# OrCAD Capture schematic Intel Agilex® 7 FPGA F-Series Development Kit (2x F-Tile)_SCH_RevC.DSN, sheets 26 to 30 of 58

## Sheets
26 PG29 HPS DDR4 COMP3,4: size C
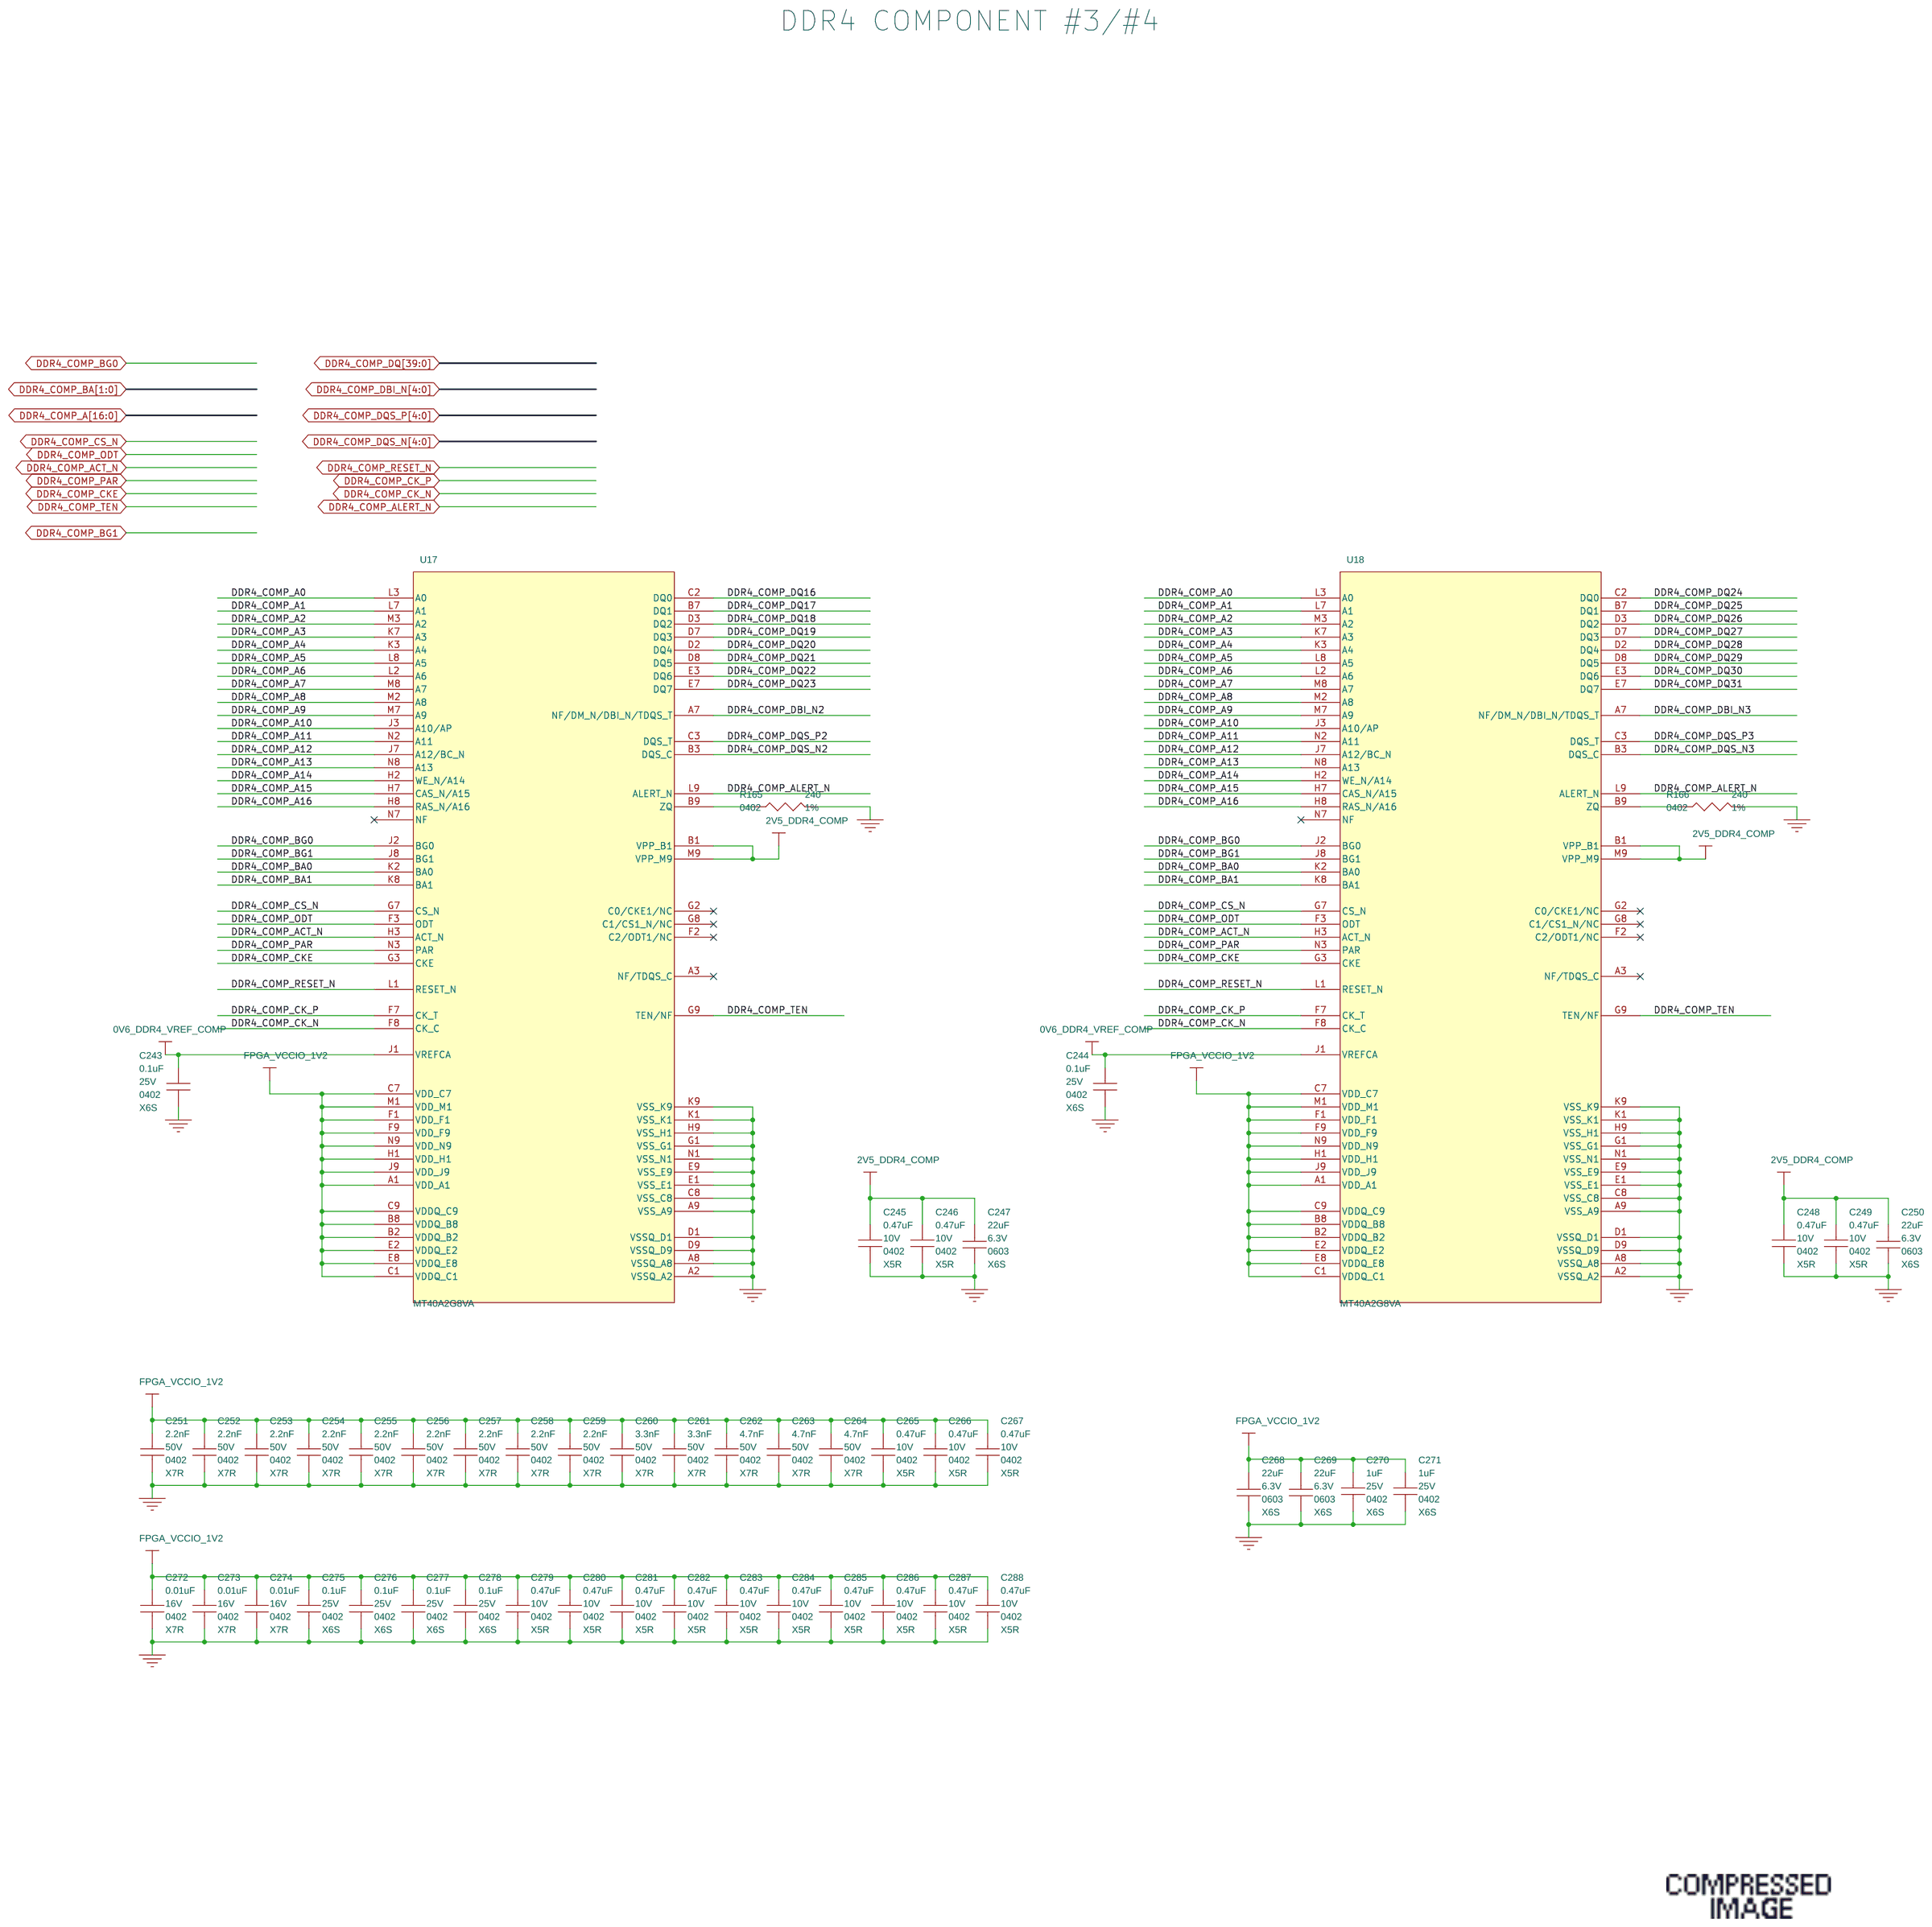
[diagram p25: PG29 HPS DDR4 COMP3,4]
27 PG30 HPSDDR4 COMP5, TERM: size C
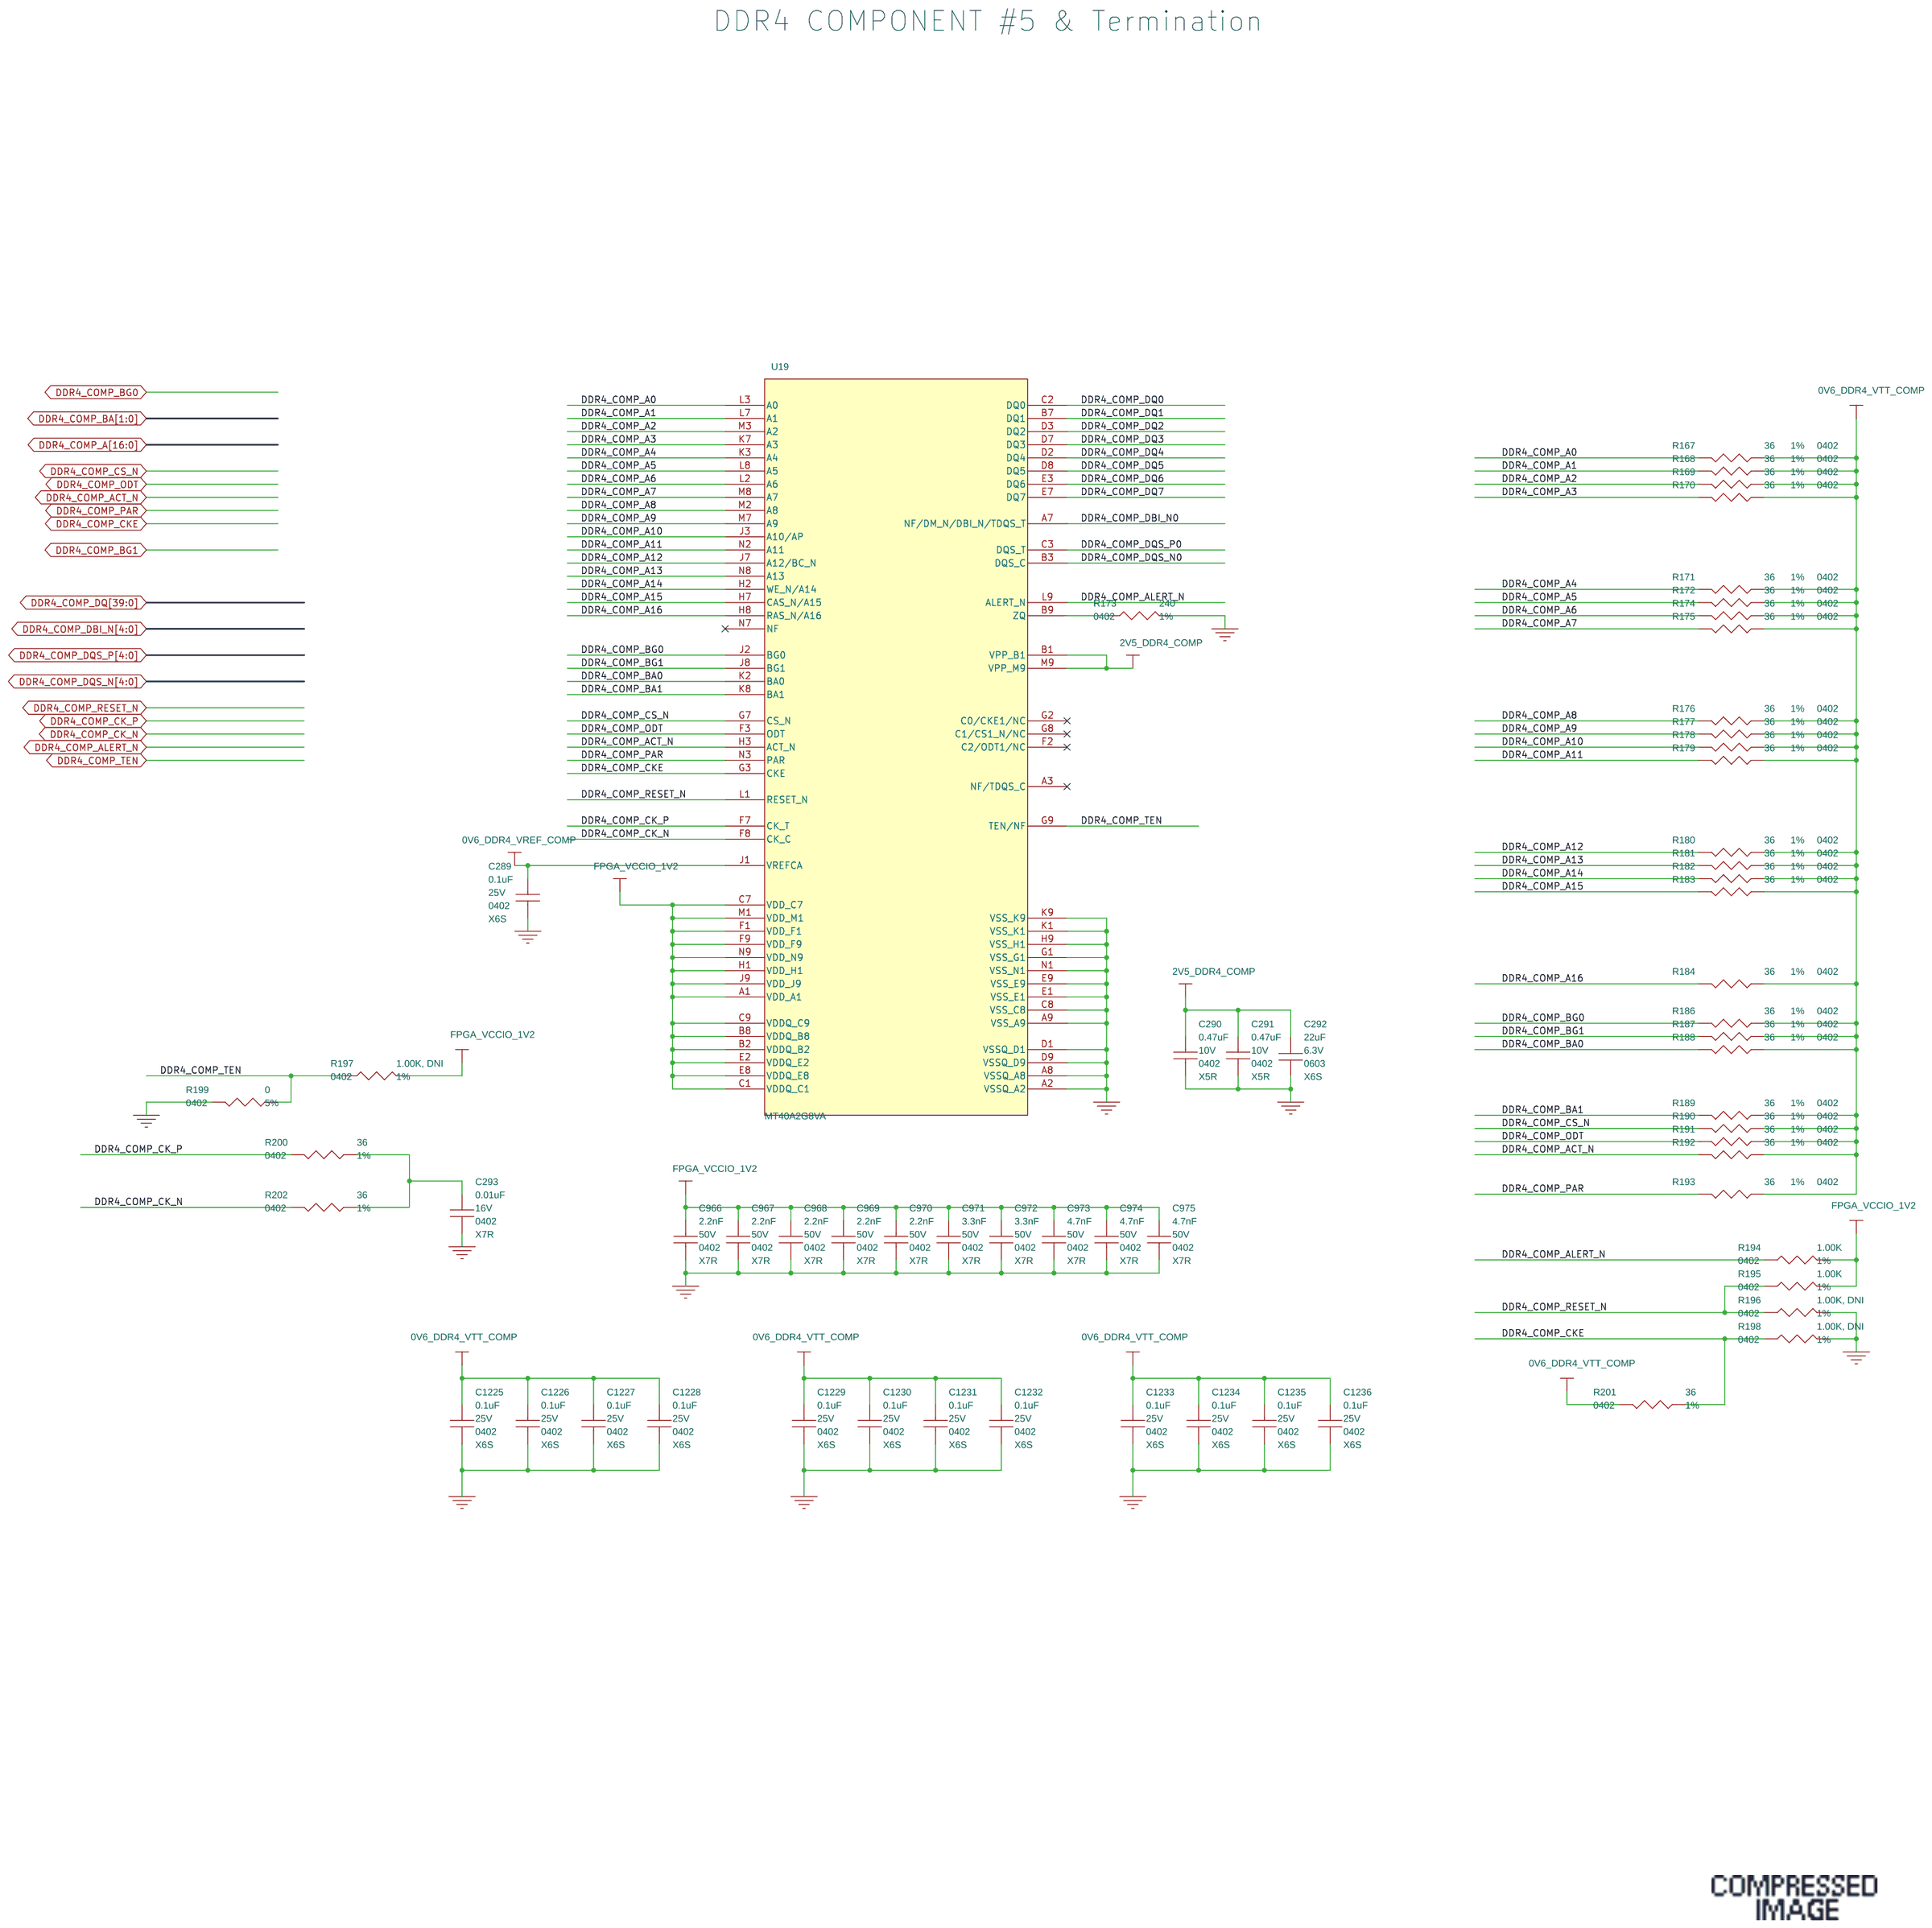
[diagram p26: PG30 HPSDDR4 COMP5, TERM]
28 PG31 HPS IO48 INTERFACE: size C
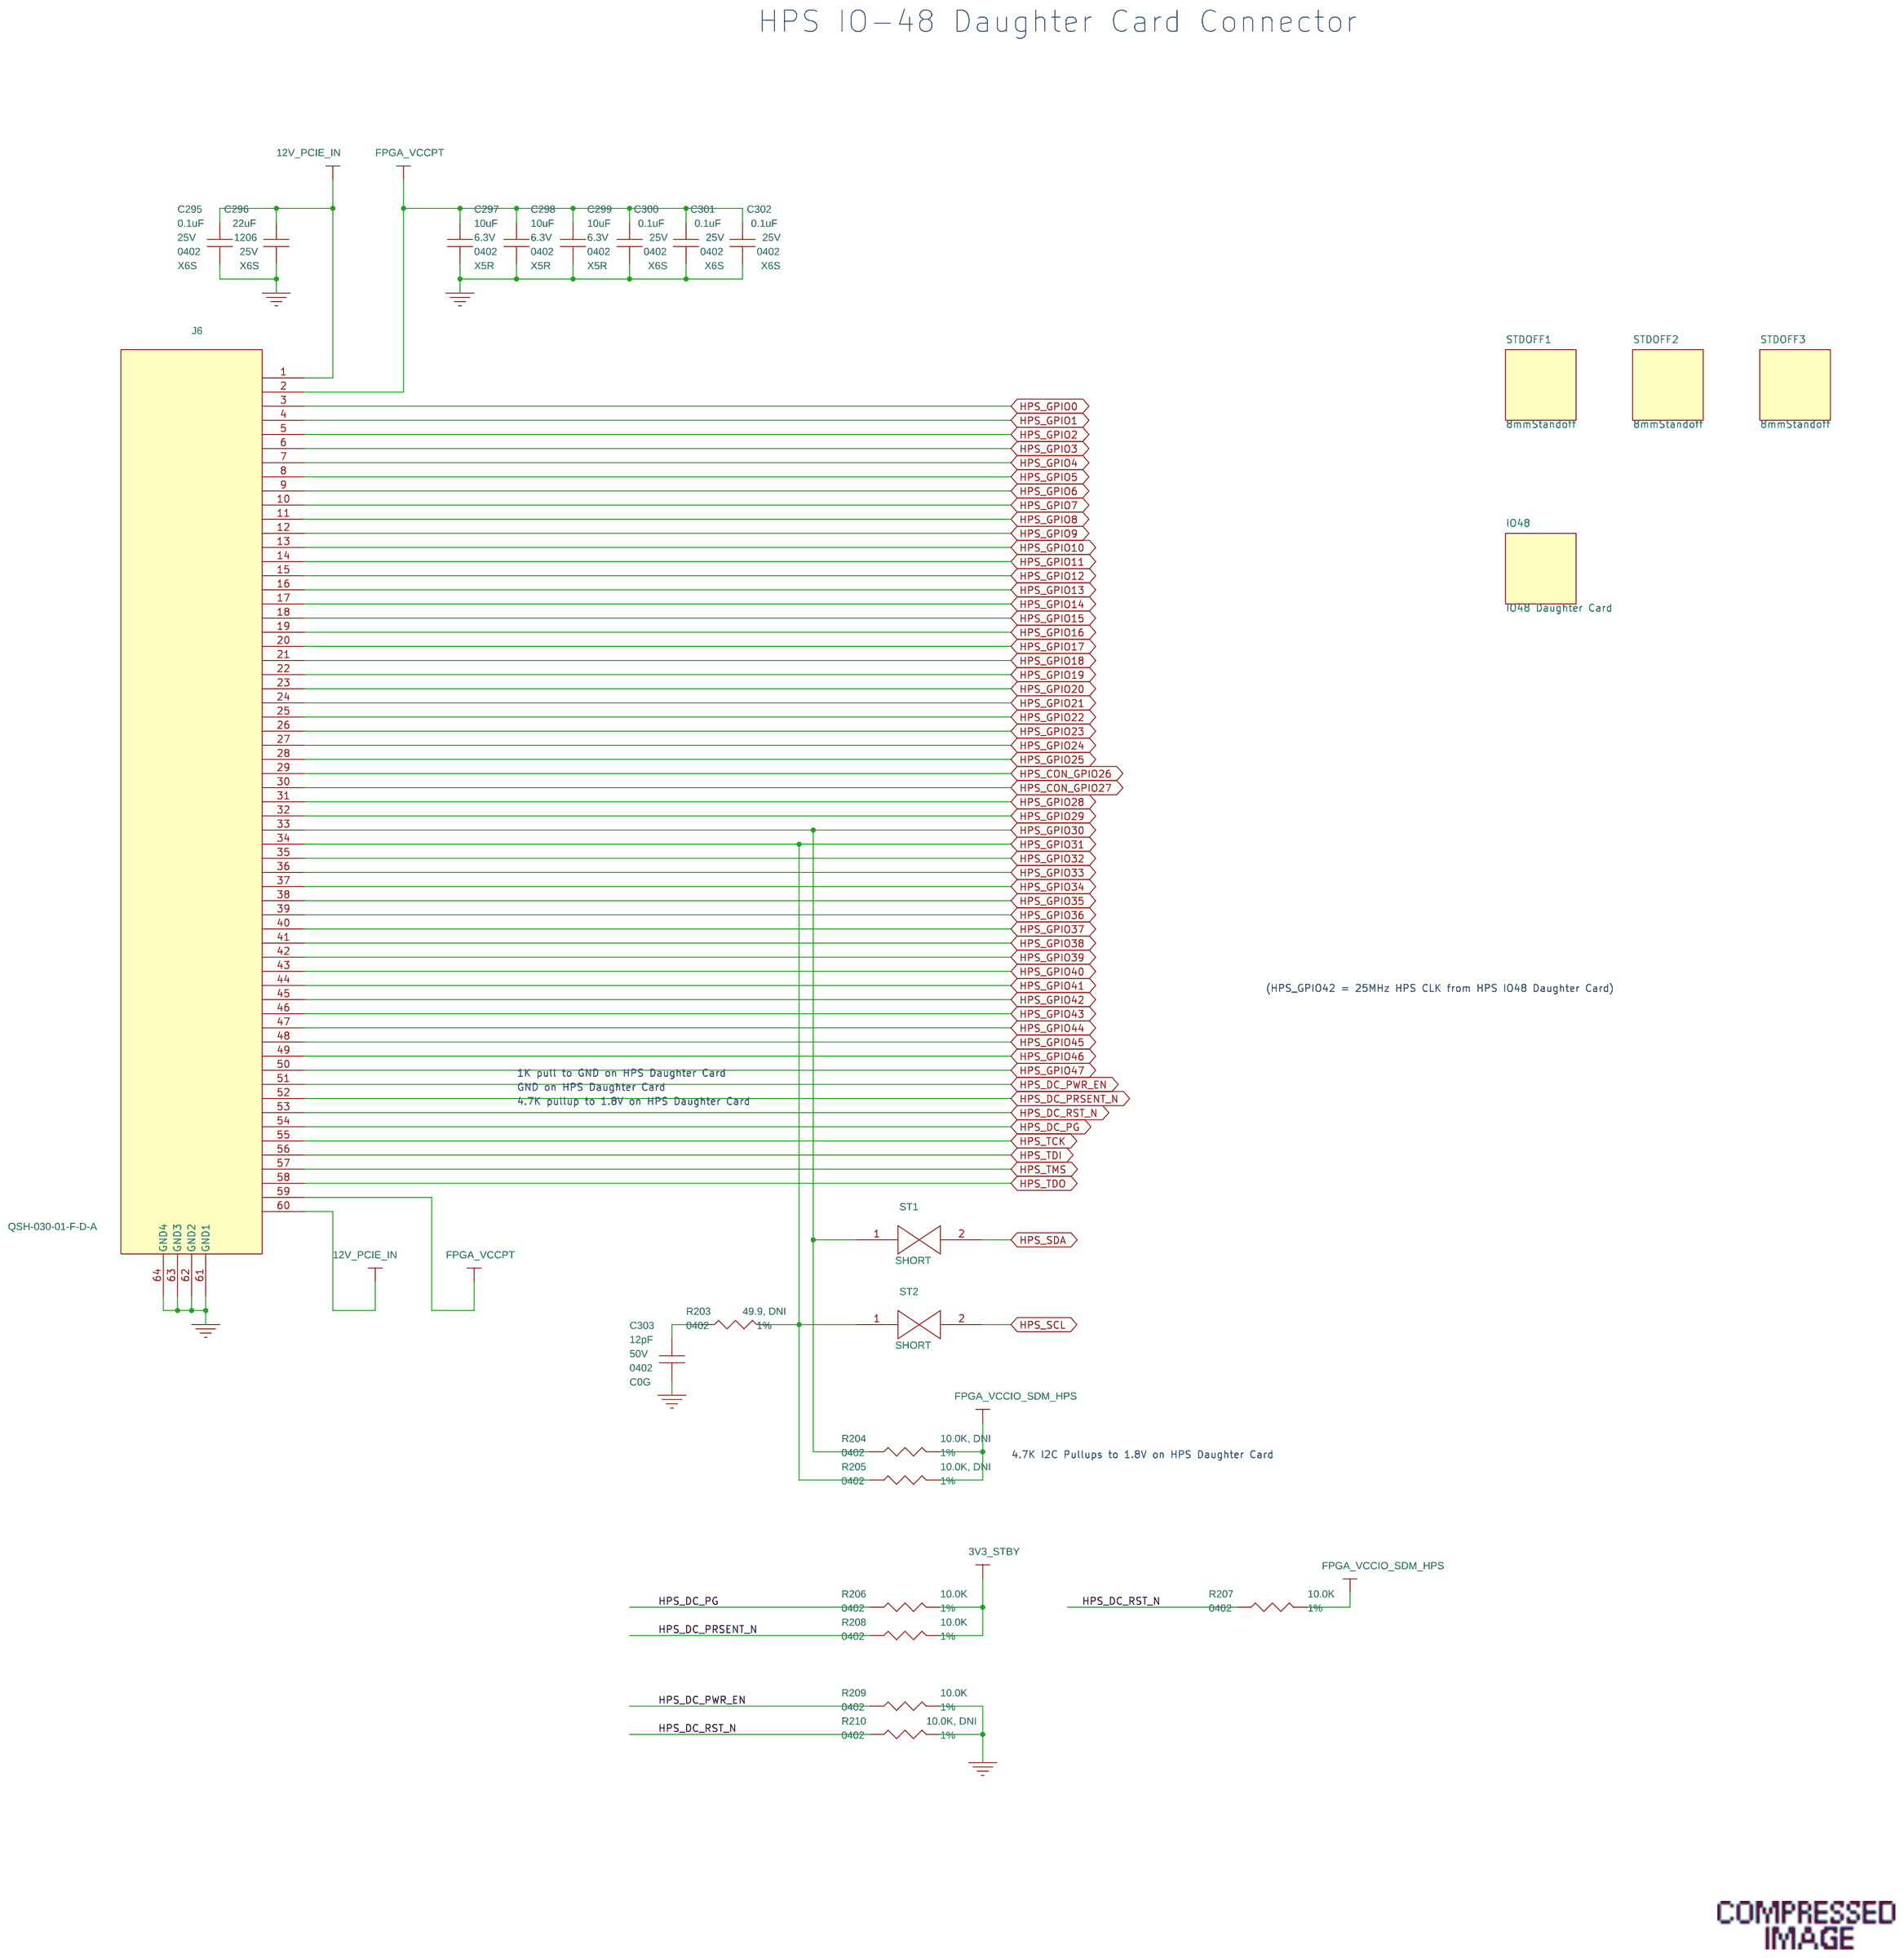
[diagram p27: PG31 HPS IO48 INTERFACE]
29 PG32 QSFPDD-56: size C
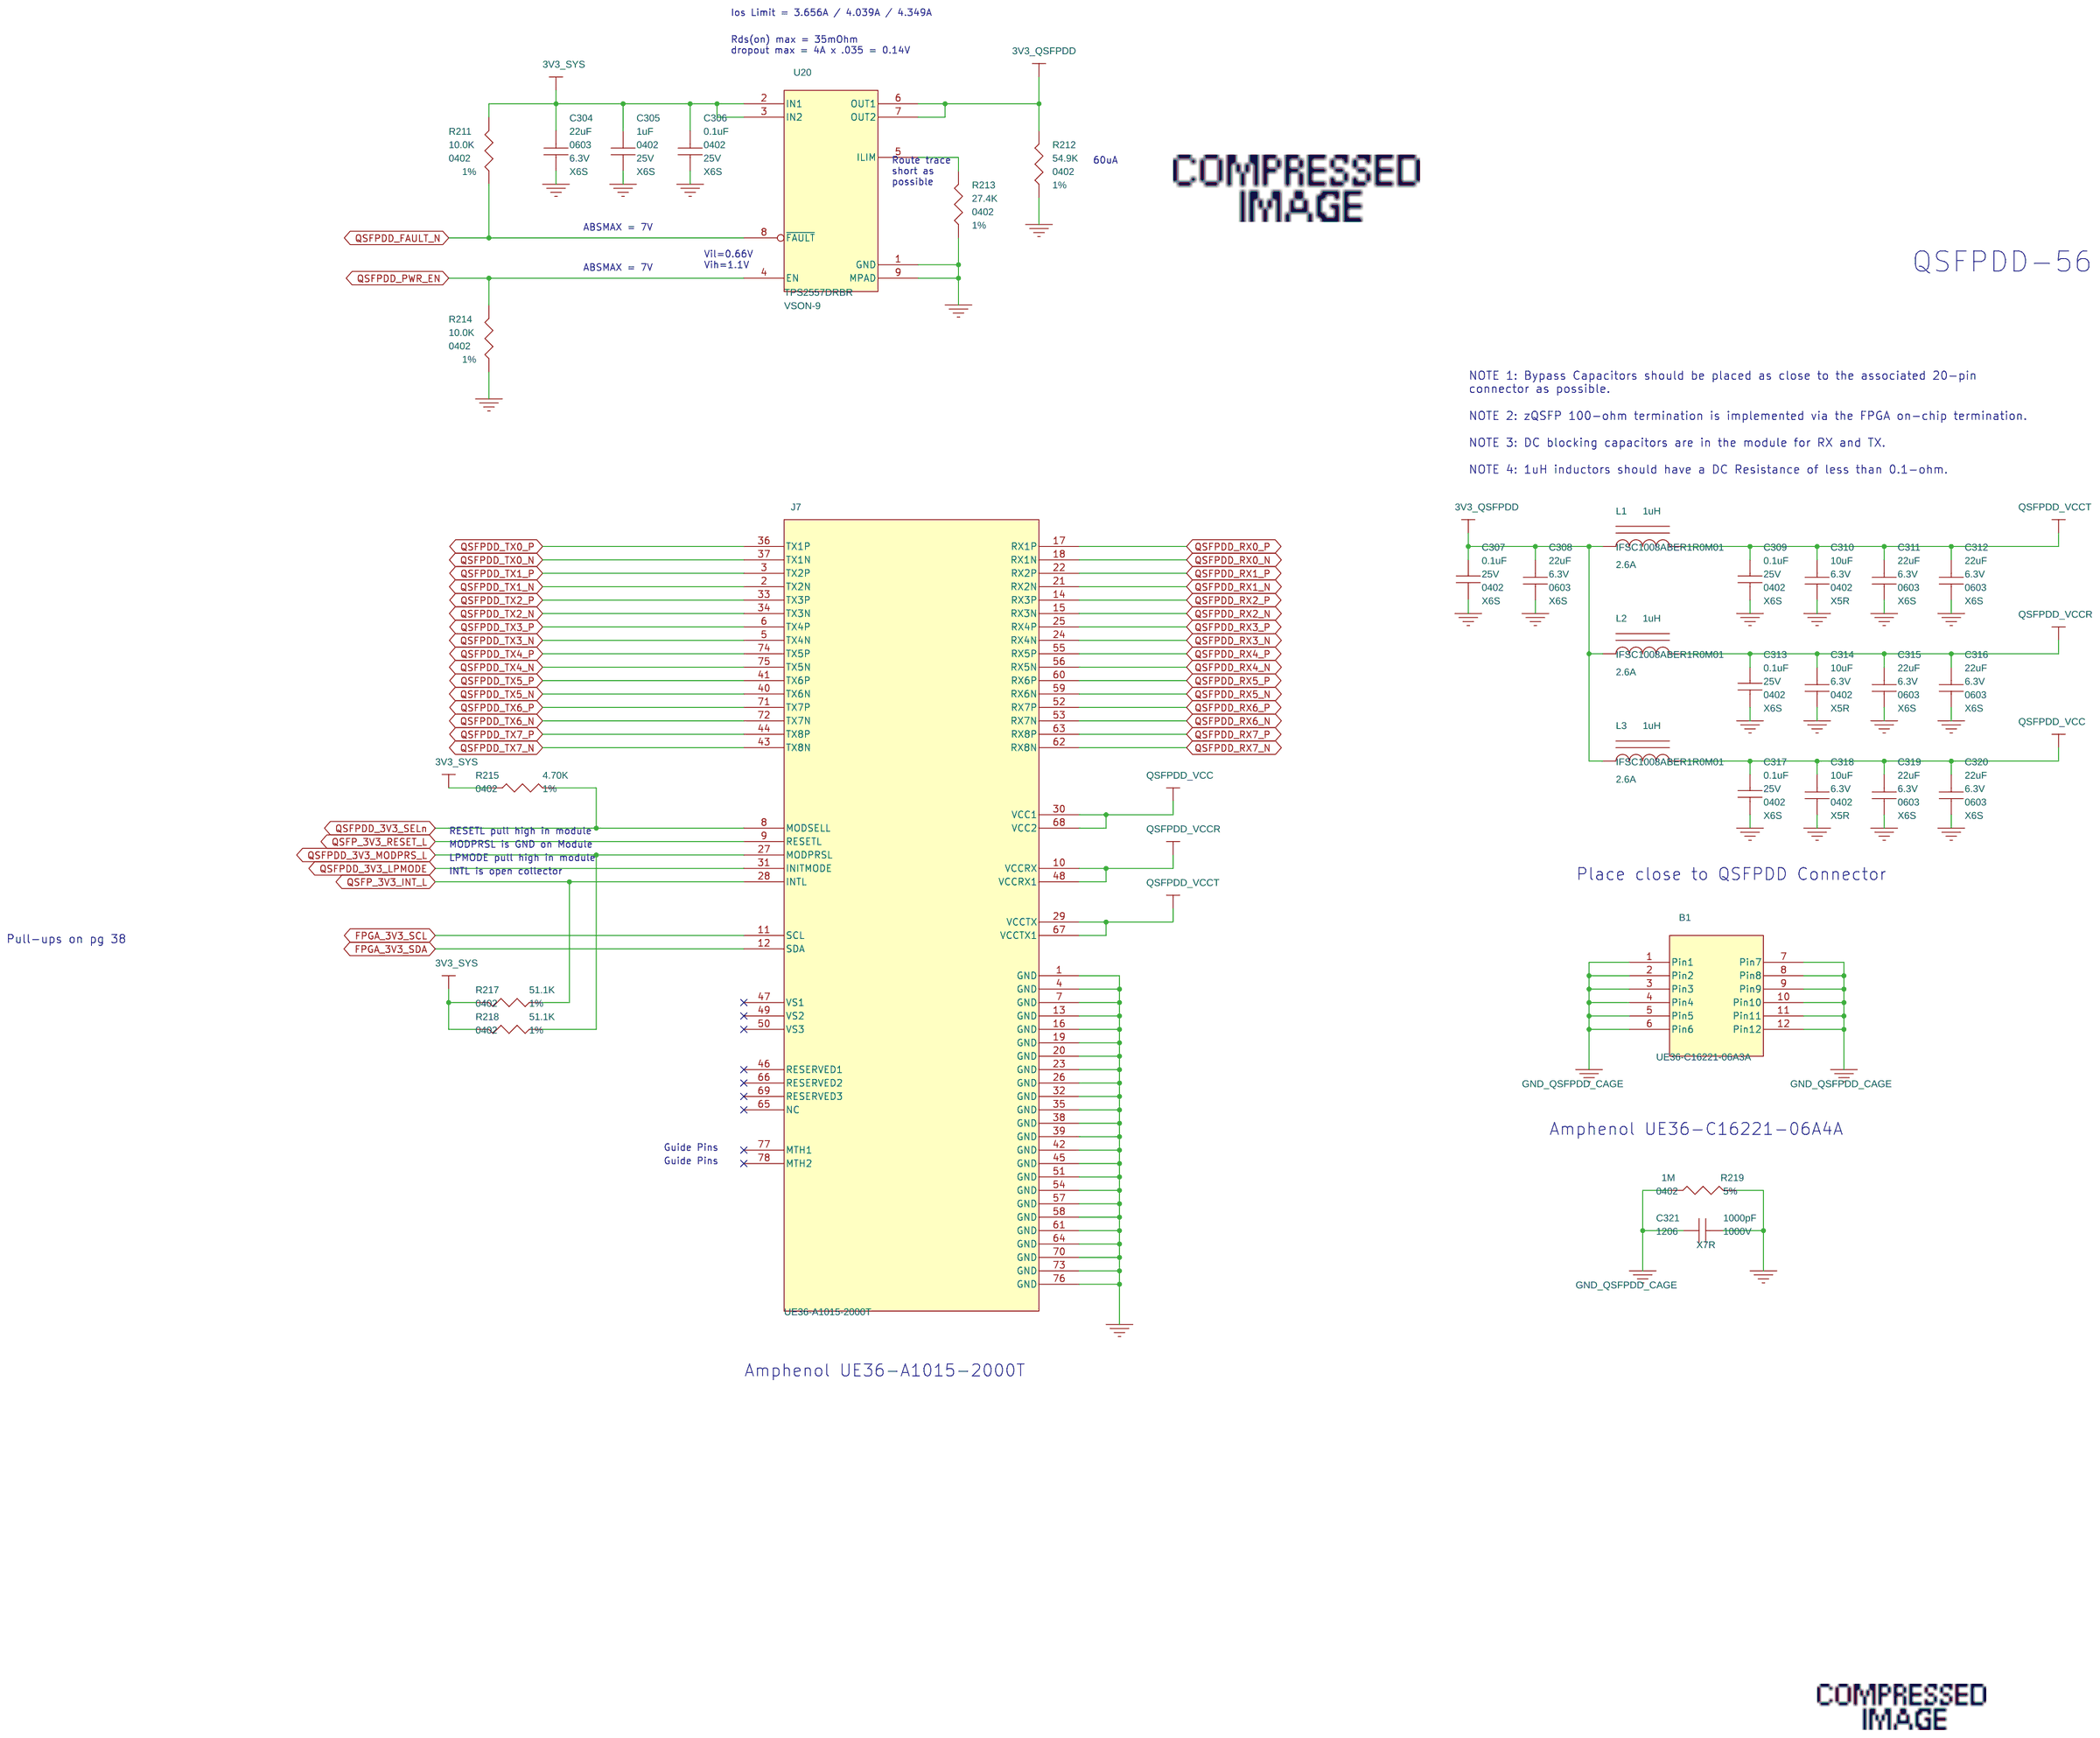
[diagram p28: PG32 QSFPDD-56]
30 PG33 QSFP-56: size C
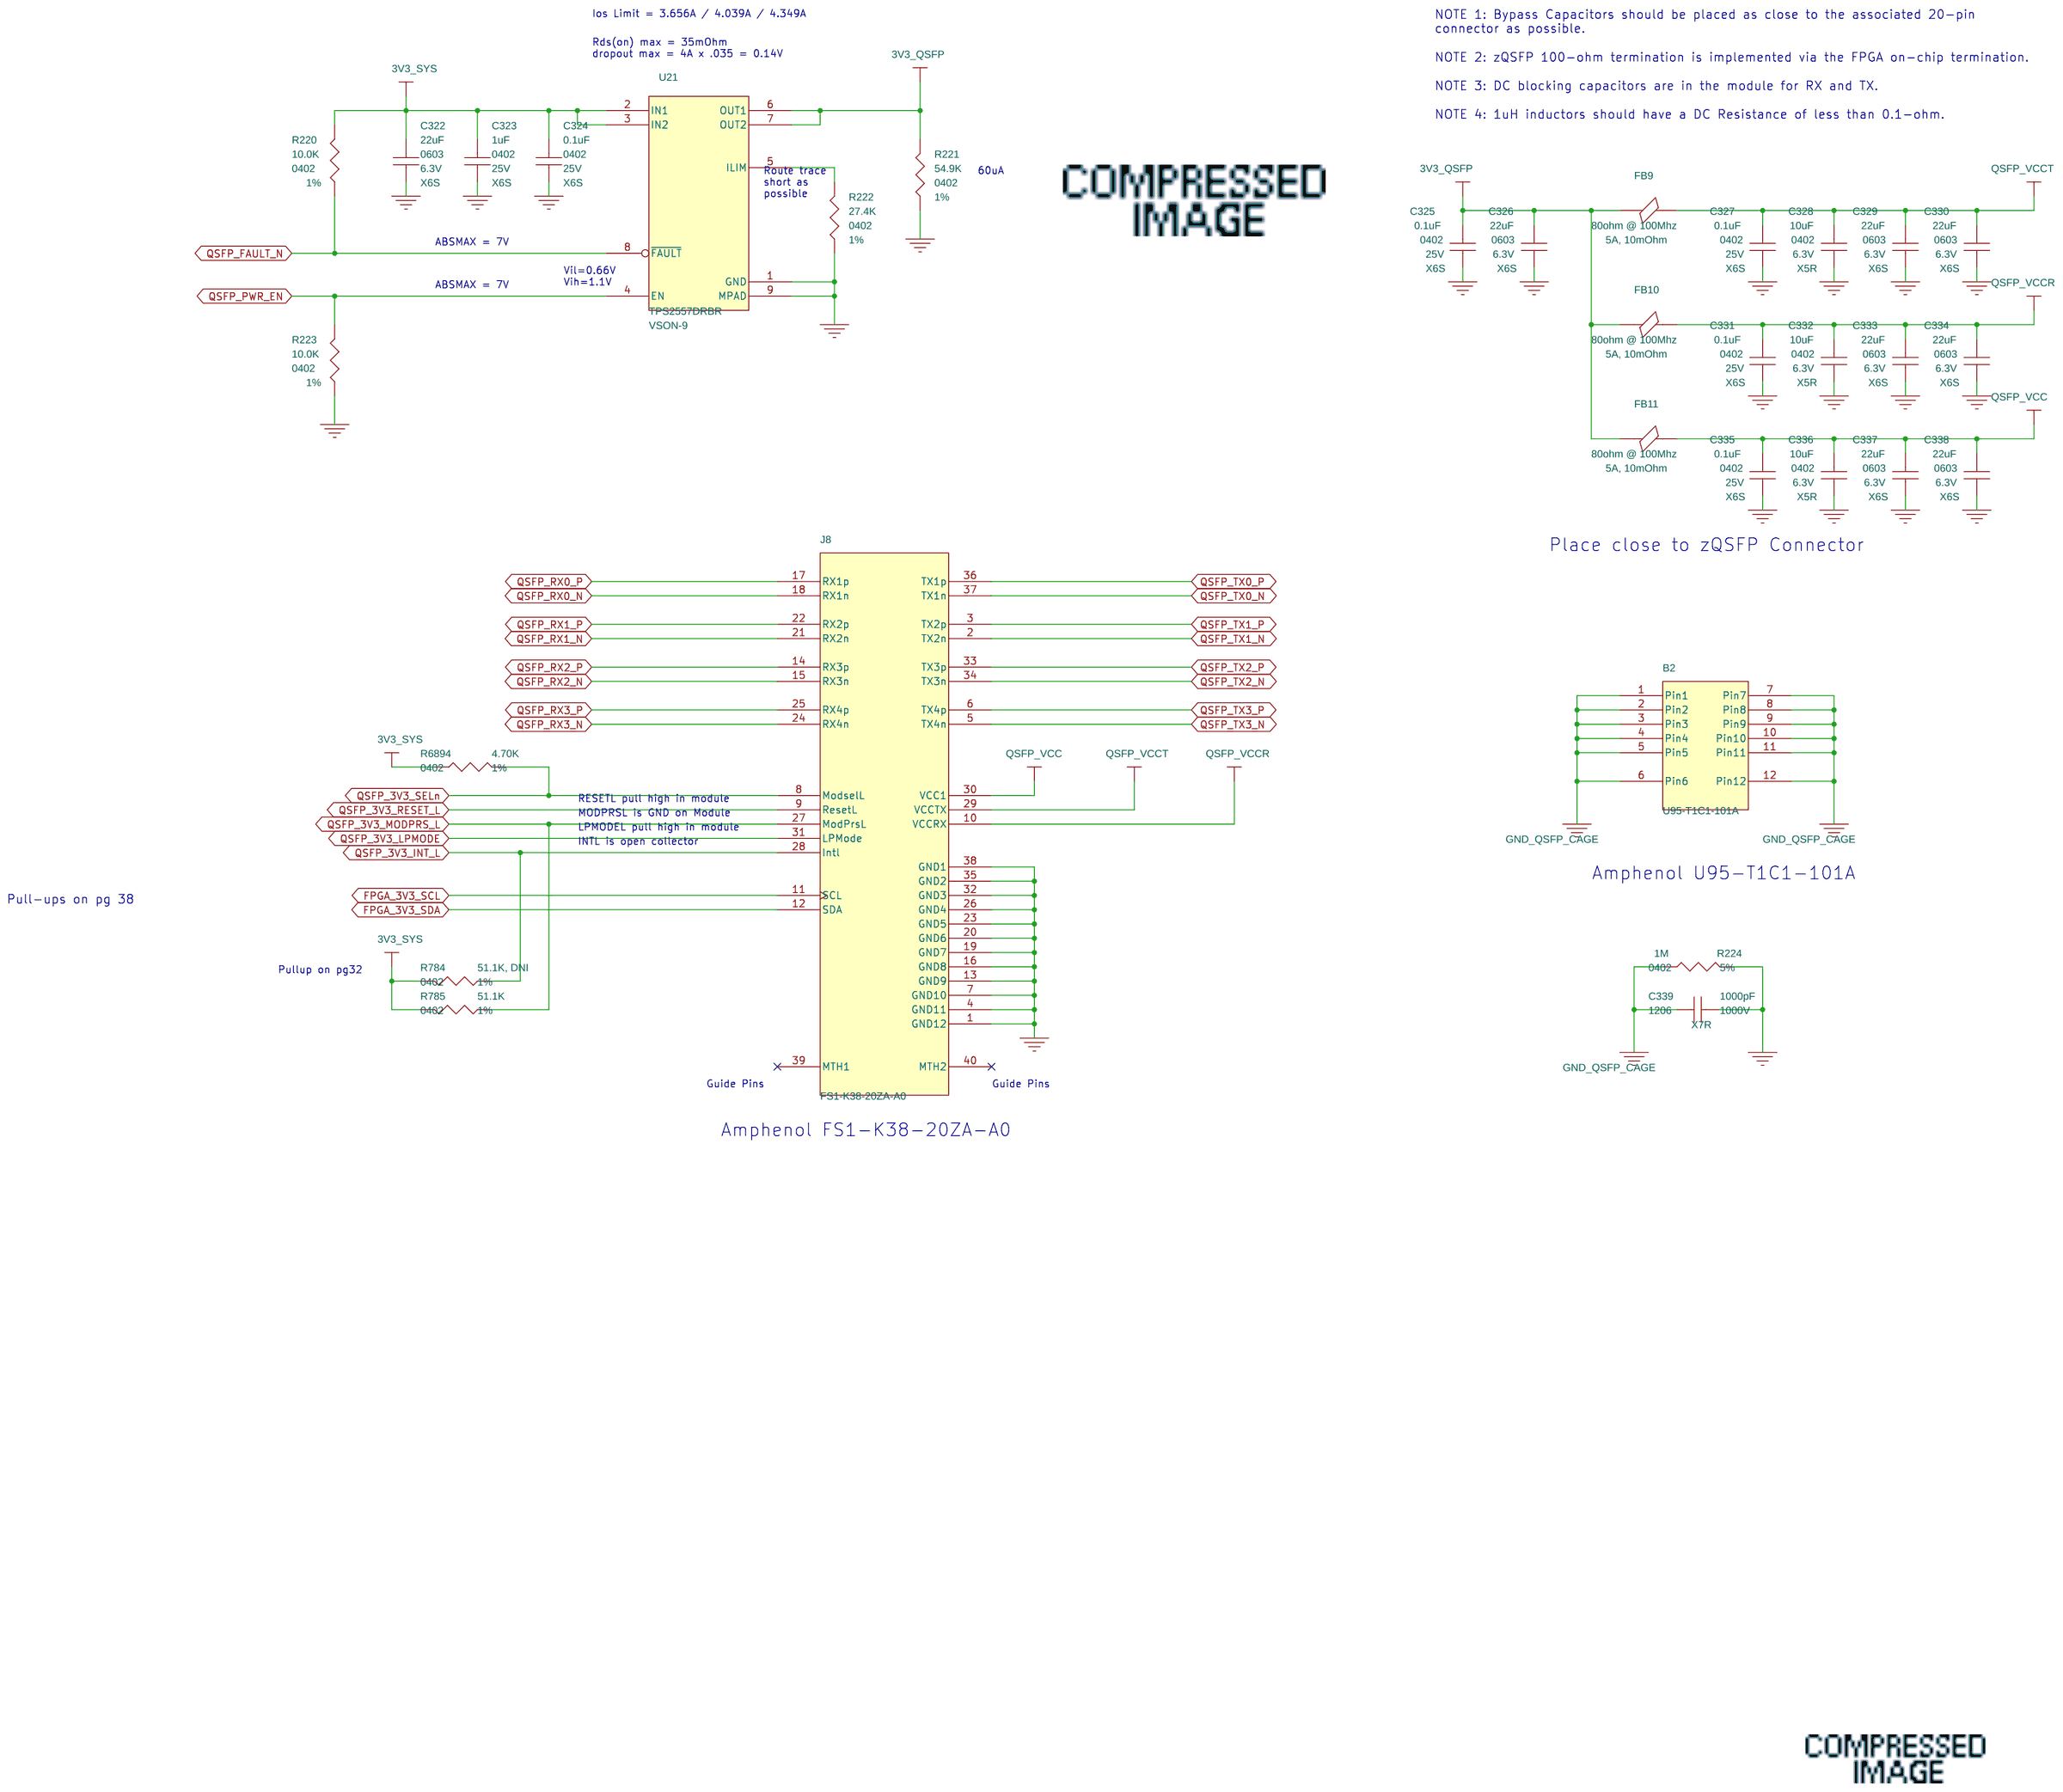
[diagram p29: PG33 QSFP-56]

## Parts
sheet PG29 HPS DDR4 COMP3,4
C243  0.1uF  [0402]
C244  0.1uF  [0402]
C245  0.47uF  [0402]
C246  0.47uF  [0402]
C247  22uF  [0603]
C248  0.47uF  [0402]
C249  0.47uF  [0402]
C250  22uF  [0603]
C251  2.2nF  [0402]
C252  2.2nF  [0402]
C253  2.2nF  [0402]
C254  2.2nF  [0402]
C255  2.2nF  [0402]
C256  2.2nF  [0402]
C257  2.2nF  [0402]
C258  2.2nF  [0402]
C259  2.2nF  [0402]
C260  3.3nF  [0402]
C261  3.3nF  [0402]
C262  4.7nF  [0402]
C263  4.7nF  [0402]
C264  4.7nF  [0402]
C265  0.47uF  [0402]
C266  0.47uF  [0402]
C267  0.47uF  [0402]
C268  22uF  [0603]
C269  22uF  [0603]
C270  1uF  [0402]
C271  1uF  [0402]
C272  0.01uF  [0402]
C273  0.01uF  [0402]
C274  0.01uF  [0402]
C275  0.1uF  [0402]
C276  0.1uF  [0402]
C277  0.1uF  [0402]
C278  0.1uF  [0402]
C279  0.47uF  [0402]
C280  0.47uF  [0402]
C281  0.47uF  [0402]
C282  0.47uF  [0402]
C283  0.47uF  [0402]
C284  0.47uF  [0402]
C285  0.47uF  [0402]
C286  0.47uF  [0402]
C287  0.47uF  [0402]
C288  0.47uF  [0402]
R165  240  [0402]
R166  240  [0402]
U17  MT40A2G8VA  [FBGA-78]
U18  MT40A2G8VA  [FBGA-78]
sheet PG30 HPSDDR4 COMP5, TERM
C289  0.1uF  [0402]
C290  0.47uF  [0402]
C291  0.47uF  [0402]
C292  22uF  [0603]
C293  0.01uF  [0402]
C966  2.2nF  [0402]
C967  2.2nF  [0402]
C968  2.2nF  [0402]
C969  2.2nF  [0402]
C970  2.2nF  [0402]
C971  3.3nF  [0402]
C972  3.3nF  [0402]
C973  4.7nF  [0402]
C974  4.7nF  [0402]
C975  4.7nF  [0402]
C1225  0.1uF  [0402]
C1226  0.1uF  [0402]
C1227  0.1uF  [0402]
C1228  0.1uF  [0402]
C1229  0.1uF  [0402]
C1230  0.1uF  [0402]
C1231  0.1uF  [0402]
C1232  0.1uF  [0402]
C1233  0.1uF  [0402]
C1234  0.1uF  [0402]
C1235  0.1uF  [0402]
C1236  0.1uF  [0402]
R167  36  [0402]
R168  36  [0402]
R169  36  [0402]
R170  36  [0402]
R171  36  [0402]
R172  36  [0402]
R173  240  [0402]
R174  36  [0402]
R175  36  [0402]
R176  36  [0402]
R177  36  [0402]
R178  36  [0402]
R179  36  [0402]
R180  36  [0402]
R181  36  [0402]
R182  36  [0402]
R183  36  [0402]
R184  36  [0402]
R186  36  [0402]
R187  36  [0402]
R188  36  [0402]
R189  36  [0402]
R190  36  [0402]
R191  36  [0402]
R192  36  [0402]
R193  36  [0402]
R194  1.00K  [0402]
R195  1.00K  [0402]
R196  1.00K, DNI  [0402]
R197  1.00K, DNI  [0402]
R198  1.00K, DNI  [0402]
R199  0  [0402]
R200  36  [0402]
R201  36  [0402]
R202  36  [0402]
U19  MT40A2G8VA  [FBGA-78]
sheet PG31 HPS IO48 INTERFACE
C295  0.1uF  [0402]
C296  22uF  [1206]
C297  10uF  [0402]
C298  10uF  [0402]
C299  10uF  [0402]
C300  0.1uF  [0402]
C301  0.1uF  [0402]
C302  0.1uF  [0402]
C303  12pF  [0402]
IO48  IO48 Daughter Card
J6  QSH-030-01-F-D-A  [QSH-030-01-C-D-A]
R203  49.9, DNI  [0402]
R204  10.0K, DNI  [0402]
R205  10.0K, DNI  [0402]
R206  10.0K  [0402]
R207  10.0K  [0402]
R208  10.0K  [0402]
R209  10.0K  [0402]
R210  10.0K, DNI  [0402]
ST1  SHORT  [SHORT]
ST2  SHORT  [SHORT]
STDOFF1  8mmStandoff
STDOFF2  8mmStandoff
STDOFF3  8mmStandoff
sheet PG32 QSFPDD-56
B1  UE36-C16221-06A3A  [QSFPDD_Cage_UE36-C16221-06A3A]
C304  22uF  [0603]
C305  1uF  [0402]
C306  0.1uF  [0402]
C307  0.1uF  [0402]
C308  22uF  [0603]
C309  0.1uF  [0402]
C310  10uF  [0402]
C311  22uF  [0603]
C312  22uF  [0603]
C313  0.1uF  [0402]
C314  10uF  [0402]
C315  22uF  [0603]
C316  22uF  [0603]
C317  0.1uF  [0402]
C318  10uF  [0402]
C319  22uF  [0603]
C320  22uF  [0603]
C321  1000pF  [1206]
J7  UE36-A1015-2000T  [UE36-A1015-2000T]
L1  1uH  [IFSC1008ABER1R0M01]
L2  1uH  [IFSC1008ABER1R0M01]
L3  1uH  [IFSC1008ABER1R0M01]
R211  10.0K  [0402]
R212  54.9K  [0402]
R213  27.4K  [0402]
R214  10.0K  [0402]
R215  4.70K  [0402]
R217  51.1K  [0402]
R218  51.1K  [0402]
R219  1M  [0402]
U20  TPS2557DRBR  [VSON-9]
sheet PG33 QSFP-56
B2  U95-T1C1-101A  [zQSFP_Cage_U95-T1C1-101A]
C322  22uF  [0603]
C323  1uF  [0402]
C324  0.1uF  [0402]
C325  0.1uF  [0402]
C326  22uF  [0603]
C327  0.1uF  [0402]
C328  10uF  [0402]
C329  22uF  [0603]
C330  22uF  [0603]
C331  0.1uF  [0402]
C332  10uF  [0402]
C333  22uF  [0603]
C334  22uF  [0603]
C335  0.1uF  [0402]
C336  10uF  [0402]
C337  22uF  [0603]
C338  22uF  [0603]
C339  1000pF  [1206]
FB9  80ohm @ 100Mhz  [0805]
FB10  80ohm @ 100Mhz  [0805]
FB11  80ohm @ 100Mhz  [0805]
J8  FS1-K38-20ZA-A0  [FS1-K38-20ZA-A0]
R220  10.0K  [0402]
R221  54.9K  [0402]
R222  27.4K  [0402]
R223  10.0K  [0402]
R224  1M  [0402]
R784  51.1K, DNI  [0402]
R785  51.1K  [0402]
R6894  4.70K  [0402]
U21  TPS2557DRBR  [VSON-9]

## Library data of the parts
C243 C244 C275-C278 C289 C295 C300-C302 C306 C307 C309 C313 C317 C324 C325 C327 C331 C335 = CAP: CAP CER 0.1UF 25V X6S 0402; Dielectric: X6S; IPN: K19434-001; Item Num: K19434-001; LIFECYCLE_PHASE: Active; Lead Free Status: Lead Free; MFR_LIFECYCLE: Active; Manufacturer: Murata; Manufacturer Part Num: GRM155C81E104KA12D; Num Pins: 2; PART_SUBCLASS: CAPACITORS; Part Class: CAPACITORS; RATED_VOLTAGE: 25V; RoHS Compliant: RoHS Compliant; Temperature Coefficient: X6S; Tolerance: 10%
C245 C246 C248 C249 C265-C267 C279-C288 C290 C291 = CAP: CAP - CER, .47UF, 10V, X5R, 0402; AGILE_LINK: http://sj-agile9app/Agile/PLMServlet?action=OpenEmailObject&classid=10000&objid=256989651; Item Num: H75789-001; LIFECYCLE_PHASE: Active; Lead Free Status: Lead Free; MFR_LIFECYCLE: Active; Manufacturer: Murata; Manufacturer Part Num: GRM155R61A474KE15D; Num Pins: 2; PART_SUBCLASS: CAPACITORS; Part Class: CAPACITORS; RATED_VOLTAGE: 10V; RoHS Compliant: RoHS Compliant; Temperature Coefficient: X5R; Tolerance: +80%/-20%
C247 C250 C268 C269 C292 C304 C308 C311 C312 C315 C316 C319 C320 C322 C326 C329 C330 C333 C334 C337 C338 = CAP: CAP CER 22UF 6.3V X6S 0603; AGILE_LINK: http://sj-agile9app/Agile/PLMServlet?action=OpenEmailObject&classid=10000&objid=257560276; Item Num: H63299-001; LIFECYCLE_PHASE: Active; Lead Free Status: Not Lead Free; MFR_LIFECYCLE: Active; Manufacturer: Murata; Manufacturer Part Num: GRM188C80J226ME15D; Num Pins: 2; PART_SUBCLASS: CAPACITORS; RATED_VOLTAGE: 6.3V; RoHS Compliant: RoHS Compliant; TOLERANCE: 20%; Temperature Coefficient: X6S
C251-C259 C966-C970 = CAP: CAP CER 2200PF 50V 10% X7R 0402; CAPACITANCE: 2200pF; Dielectric: X7R; Item Num: K13631-001; LIFECYCLE_PHASE: Active; Lead Free Status: Lead Free; Manufacturer: TDK; Manufacturer Part Num: CGJ2B2X7R1E222K050BA; Num Pins: 2; PART_SUBCLASS: CAPACITORS; Part Class: CAPACITORS; RATED_VOLTAGE: 50V; RoHS Compliant: RoHS Compliant; TOLERANCE: +/-10%; Temperature Coefficient: X7R
C260 C261 C971 C972 = CAP: CAP, CERAMIC, 3300PF, 10%, 50V, X7R, 0402; Item Num: K13754-001; LIFECYCLE_PHASE: Active; Lead Free Status: Lead Free; MFR_LIFECYCLE: Active; Manufacturer: Murata; Manufacturer Part Num: GRM155F51H332ZA01x; Num Pins: 2; PART_SUBCLASS: CAPACITORS; RATED_VOLTAGE: 50V; RoHS Compliant: RoHS Compliant; TOLERANCE: +/-10%; Temperature Coefficient: X7R
C262-C264 C973-C975 = CAP: CAP - CER 4700PF 50V 10% X7R 0402; AGILE_LINK: http://sj-agile9app/Agile/PLMServlet?action=OpenEmailObject&classid=10000&objid=215384813; Item Num: G24897-001; LIFECYCLE_PHASE: Active; Lead Free Status: Lead Free; MFR_LIFECYCLE: Active; Manufacturer: Murata; Manufacturer Part Num: GRM155R71H472KA01D; Num Pins: 2; PACKAGING: Tape & Reel (TR); PART_SUBCLASS: CAPACITORS; RATED_VOLTAGE: 50V; RoHS Compliant: RoHS Compliant; Supplier Part Num: GRM155R71H472KA01D; Temperature Coefficient: X7R; Tolerance: 10%
C270 C271 = CAP: CAP CER 1UF 25V X6S 0402; Item Num: H81594-001; Lead Free Status: Yes; Manufacturer: Murata; Manufacturer Part Num: GRM155C81E105KE11D; Num Pins: 2; Part Class: CAPACITORS; RATED_VOLTAGE: 25V; RoHS Compliant: Yes; Temperature Coefficient: X6S; Voltage: 25V
C272-C274 C293 = CAP: CAP, CER .01UF 16V X7R 0402; Item Num: A36096-007; Lead Free Status: Yes; Manufacturer: Murata; Manufacturer Part Num: GRM155R71C103KA01D; Manufacturer's Part No.: GRM155R71C103KA01D; Num Pins: 2; Part Class: CAPACITORS; RoHS Compliant: Yes; Temperature Coefficient: X7R; Tolerance: 10%; Voltage: 16V
R165 R166 R173 = RESISTOR: RES - 240 OHM, 1/16W, 1%, 0402 SMD; Item Num: K15783-001; LIFECYCLE_PHASE: Active; Lead Free Status: Yes; MFR_LIFECYCLE: Active; Manufacturer: Panasonic; Manufacturer Part Num: ERJ-2RKF2400X; Num Pins: 2; PART_SUBCLASS: RESISTORS; RoHS Compliant: Yes; Tolerance: 1%
U17-U19 = MT40A2G8VA: IC, DDR4, DRAM, 2Gx8, FPGA, 78-BALL; Item Num: K74985-002; Manufacturer: Micron; Manufacturer Part Num: MT40A2G8JC-062E IT:E
C1225-C1236 = CAP: CAP CER 0.1UF 25V X6S 0402; Dielectric: X6S; IPN: K19434-001; Item Num: K19434-001; LIFECYCLE_PHASE: Active; Lead Free Status: Lead Free; MFR_LIFECYCLE: Active; Manufacturer: Murata; Manufacturer Part Num: GRM155C81E104KA12D; PART_SUBCLASS: CAPACITORS; Part Class: CAPACITORS; RATED_VOLTAGE: 25V; RoHS Compliant: RoHS Compliant; Temperature Coefficient: X6S; Tolerance: 10%; Voltage: 25V
R167-R172 R174-R184 R186-R193 R200-R202 = RESISTOR: RES_D,0402,36.00OHM,1.00%,1/16W,; Item Num: A93548-623; Lead Free Status: Yes; Manufacturer: VISHAY; Manufacturer Part Num: CRCW040236R0FKED; Num Pins: 2; Part Class: Resistors; Price: 0; Tolerance: 1%
R194-R198 = RESISTOR: RES,1.00K OHMS,1.0%,1/16W,0402; Item Num: G60609-021; Lead Free Status: Yes; Manufacturer: Panasonic; Manufacturer Part Num: ERJ-2RKF1001X; Num Pins: 2; Part Class: Resistors; Tolerance: 1%
R199 = RES_0_OHM_5%_1_16W_0402_SMD: Item Num: A93549-001; Manufacturer: Yageo; Manufacturer Part Num: RC0402JR-070RL; Num Pins: 2; RoHS Compliant: Yes; Tolerance: 5%
C296 = CAP: CAP CER 22UF 25V X6S 1206; AGILE_LINK: http://sj-agile9app/Agile/PLMServlet?action=OpenEmailObject&classid=10000&objid=257560276; Item Num: H65936-001; LIFECYCLE_PHASE: Active; Lead Free Status: Lead Free; MFR_LIFECYCLE: Active; Manufacturer: Murata; Manufacturer Part Num: GRM31CC81E226KE11L; Num Pins: 2; PART_SUBCLASS: CAPACITORS; RATED_VOLTAGE: 25V; RoHS Compliant: RoHS Compliant; TOLERANCE: 10%; Thermal Coefficient: X6S
C297-C299 = CAP: CAP CER 10UF 6.3V X5R 0402; AGILE_LINK: http://sj-agile9app/Agile/PLMServlet?action=OpenEmailObject&classid=10000&objid=258353688; Item Num: K46607-001; LIFECYCLE_PHASE: Active; Lead Free Status: Lead Free; MFR_LIFECYCLE: Active; Manufacturer: Murata Electronics North America; Manufacturer Part Num: GRJ155R60J106ME11D; Num Pins: 2; PART_SUBCLASS: CAPACITORS; Part Class: CAPACITORS; RATED_VOLTAGE: 6.3V; RoHS Compliant: RoHS Compliant; TOLERANCE: 20%; Temperature Coefficient: X5R
C303 = CAP: CAPC,C0G,0402,12.000PF,50.000V,+/- 5%; AGILE_LINK: http://sj-agile9app/Agile/PLMServlet?action=OpenEmailObject&classid=10000&objid=257385742; Item Num: A36095-043; LIFECYCLE_PHASE: Active; Lead Free Status: Lead Free; MFR_LIFECYCLE: Active; Manufacturer: Murata; Manufacturer Part Num: GRM1555C1H120JA01F; Num Pins: 2; PART_SUBCLASS: CAPACITORS; RATED_VOLTAGE: 50V; RoHS Compliant: RoHS Compliant; TOLERANCE: +/-5%; Temperature Coefficient: C0G
IO48 = BLANK_PART: IO48 Daughter Card Sub-assembly; Item Num: K11763-001; Manufacturer: Samtec; Manufacturer Part Num: Intel; Manufacturer's Part No.: K11763-001
J6 = QSH-030-01-C-D-A: CONN - SAMTEC QSH, 30-Pin Pairs, Single-Ended; Item Num: K11630-001; Manufacturer: Samtec
R203 = RESISTOR: RES SMD 49.9 OHM 1% 1/10W 0402; Item Num: K16545-001; LIFECYCLE_PHASE: Active; Lead Free Status: Yes; MFR_LIFECYCLE: Active; Manufacturer: NIC Components Corp.; Manufacturer Part Num: NRC04F49R9TRF; Num Pins: 2; PART_SUBCLASS: RESISTORS; POWER: 1/16W; Part Class: Resistors; RESISTANCE: 49.9; RoHS Compliant: Yes; Tolerance: 1%
R204 R205 R210 = RESISTOR: RES,10.0K OHMS,1.0%,1/16W, 0402; AGILE_LINK: http://sj-agile9app/Agile/PLMServlet?action=OpenEmailObject&classid=10000&objid=146548997; Item Num: K28115-001; LIFECYCLE_PHASE: Active; Lead Free Status: Yes; MFR_LIFECYCLE: Active; Manufacturer: Panasonic; Manufacturer Part Num: ERJ-2RKF1002X; Num Pins: 2; PART_SUBCLASS: RESISTORS; POWER: 1/16W; RESISTANCE: 10.0K; RoHS Compliant: Yes; TOLERANCE: 1%
R206-R209 R211 R214 R220 R223 = RESISTOR: RES,10.0K OHMS,1.0%,1/16W, 0402; AGILE_LINK: http://sj-agile9app/Agile/PLMServlet?action=OpenEmailObject&classid=10000&objid=146548997; Item Num: K28115-001; LIFECYCLE_PHASE: Active; Lead Free Status: Yes; MFR_LIFECYCLE: Active; Manufacturer: Panasonic; Manufacturer Part Num: ERJ-2RKF1002X; Num Pins: 2; PART_SUBCLASS: RESISTORS; POWER: 1/16W; RoHS Compliant: Yes; TOLERANCE: 1%
ST1 ST2 = SHORT
STDOFF1-STDOFF3 = BLANK_PART: 8.15 MM HEIGHT STANDOFF, FEMALE/MALE THREAD, #4-40 HOLE SIZE; Item Num: K14348-001; Manufacturer: Samtec; Manufacturer Part Num: ASP-186606-01; Manufacturer's Part No.: NHD-0216K3Z-NSW-BBW-V3
B1 = Molex_QSFPDD_Cage: CONN, 1X1 QSFP,DD CAGE ASSEMBLY; Item Num: M53327-001; Manufacturer: Amphenol
C305 C323 = CAP: CAP CER 1UF 25V X6S 0402; Item Num: H81594-001; Lead Free Status: Yes; Manufacturer: Murata; Manufacturer Part Num: GRM155C81E105KE11D; Num Pins: 2; Part Class: CAPACITORS; RATED_VOLTAGE: 25V; RoHS Compliant: Yes; Temperature Coefficient: X6S
C310 C314 C318 C328 C332 C336 = CAP: CAP CER 10UF 6.3V X5R 0402; AGILE_LINK: http://sj-agile9app/Agile/PLMServlet?action=OpenEmailObject&classid=10000&objid=257560276; Item Num: K46607-001; LIFECYCLE_PHASE: Active; Lead Free Status: Lead Free; MFR_LIFECYCLE: Active; Manufacturer: Murata Electronics North America; Manufacturer Part Num: GRJ155R60J106ME11D; Num Pins: 2; PART_SUBCLASS: CAPACITORS; Part Class: CAPACITORS; RATED_VOLTAGE: 6.3V; RoHS Compliant: RoHS Compliant; TOLERANCE: 20%; Temperature Coefficient: X5R
C321 C339 = CAP: CAP CER 1000PF 1000V X7R 1206; AGILE_LINK: http://sj-agile9app/Agile/PLMServlet?action=OpenEmailObject&classid=10000&objid=215384813; Item Num: K13749-001; LIFECYCLE_PHASE: Active; Lead Free Status: Lead Free; MFR_LIFECYCLE: Active; Manufacturer: Murata; Manufacturer Part Num: GRM31BR73A102KW01L; Num Pins: 2; PACKAGING: Tape & Reel (TR); PART_SUBCLASS: CAPACITORS; RATED_VOLTAGE: 1000V; RoHS Compliant: RoHS Compliant; Supplier Part Num: GRM31BR73A102KW01L; Temperature Coefficient: X7R; Tolerance: +/-10%
J7 = 2027180100: CONN, QSFP DD SMT CONNECTOR,CONN, QSFP DD SMT CONNECTOR; Item Num: K21523-001; Manufacturer: Amphenol
L1-L3 = INDUCTOR_IRON: INDCT,1.00UH,2.6A,37.00MOHM,DRUM,SM; Current: 2.6A; Item Num: D23343-007; Manufacturer: Vishay Dale
R212 R221 = RESISTOR: RES SMD 54.9K OHM 1% 1/10W 0402; AGILE_LINK: http://sj-agile9app/Agile/PLMServlet?action=OpenEmailObject&classid=10000&objid=146548997; Item Num: K12137-001; LIFECYCLE_PHASE: Active; Lead Free Status: Yes; MFR_LIFECYCLE: Active; Manufacturer: Panasonic; Manufacturer Part Num: ERJ-2RKF5492X; Num Pins: 2; PART_SUBCLASS: RESISTORS; POWER: 1/10W; RoHS Compliant: Yes; TOLERANCE: 1%
R213 R222 = RESISTOR: RES 27.4K OHM 1/16W 1% 0402 SMD; AGILE_LINK: http://sj-agile9app/Agile/PLMServlet?action=OpenEmailObject&classid=10000&objid=146548997; Item Num: H30710-001; LIFECYCLE_PHASE: Active; Lead Free Status: Yes; MFR_LIFECYCLE: Active; Manufacturer: Panasonic; Manufacturer Part Num: ERJ-2RKF2742X; Num Pins: 2; PART_SUBCLASS: RESISTORS; POWER: 1/16W; RoHS Compliant: Yes; TOLERANCE: 1%
R215 R6894 = RESISTOR: RES,4.70K OHMS,1.0%,1/16W,0402; AGILE_LINK: http://sj-agile9app/Agile/PLMServlet?action=OpenEmailObject&classid=10000&objid=146753272; Item Num: A93548-517; LIFECYCLE_PHASE: Active; Lead Free Status: Yes; MFR_LIFECYCLE: Active; Manufacturer: Vishay; Manufacturer Part Num: CRCW04024K70FKED; Num Pins: 2; PART_SUBCLASS: RESISTORS; POWER: 1/16W; RESISTANCE: 4.7K; RoHS Compliant: Yes; TOLERANCE: 1%
R217 R218 R785 = RESISTOR: CHIP RESISTOR, 0402, 1%,51.1K OHM, 1/10W; AGILE_LINK: http://sj-agile9app/Agile/PLMServlet?action=OpenEmailObject&classid=10000&objid=146548997; Item Num: M58194-001; LIFECYCLE_PHASE: Active; Lead Free Status: Yes; MFR_LIFECYCLE: Active; Manufacturer: Panasonic; Manufacturer Part Num: ERJ-2RKF5112X; Num Pins: 2; PART_SUBCLASS: RESISTORS; POWER: 1/10W; RoHS Compliant: Yes; TOLERANCE: 1%
R219 R224 = RESISTOR: RES,1M OHMS,5.0%,1/16W,0402; AGILE_LINK: http://sj-agile9app/Agile/PLMServlet?action=OpenEmailObject&classid=10000&objid=146548997; Item Num: K15866-001; LIFECYCLE_PHASE: Active; Lead Free Status: No; MFR_LIFECYCLE: Active; Manufacturer: Panasonic; Manufacturer Part Num: ERJ-2GEJ105X; Num Pins: 2; PART_SUBCLASS: RESISTORS; POWER: 1/16W; RoHS Compliant: Yes; TOLERANCE: 5%
U20 U21 = TPS2557: IC, Adjustable Current-Limited Power Distribution Switch; Item Num: G78426-001; Manufacturer: Texas Instruments
B2 = Molex_zQSFP_Cage_0: Molex zQSFP Cage; Item Num: M53330-001; Manufacturer: Amphenol
FB9-FB11 = BEAD_FERRITE_SM: FERRITE BEAD 80 OHM 0805 1LN; Item Num: K75334-001; LIFECYCLE_PHASE: Active; MFR_LIFECYCLE: Active; Manufacturer: Laird; Manufacturer Part Num: HI0805R800R-10; Num Pins: 2; PART_SUBCLASS: INDUCTORS; Part Class: Inductors; RoHS Compliant: Yes; Value2: 5A, 10mOhm
J8 = Molex_zQSFP_Conn: Item Num: K96692-001; Manufacturer: Amphenol
R784 = RESISTOR: CHIP RESISTOR, 0402, 1%,51.1K OHM, 1/10W; AGILE_LINK: http://sj-agile9app/Agile/PLMServlet?action=OpenEmailObject&classid=10000&objid=146548997; Item Num: M58194-001; LIFECYCLE_PHASE: Active; Lead Free Status: Yes; MFR_LIFECYCLE: Active; Manufacturer: Panasonic; Manufacturer Part Num: ERJ-2RKF5112X; Num Pins: 2; PART_SUBCLASS: RESISTORS; POWER: 1/10W; RESISTANCE: 51.1K; RoHS Compliant: Yes; TOLERANCE: 1%

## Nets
0V6_DDR4_VREF_COMP: C243.1 C244.1 C289.1 U17.J1(VREFCA) U18.J1(VREFCA) U19.J1(VREFCA) ; also on sheet 25 54
0V6_DDR4_VTT_COMP: C1225.1 C1226.1 C1227.1 C1228.1 C1229.1 C1230.1 C1231.1 C1232.1 C1233.1 C1234.1 C1235.1 C1236.1 R167.1 R168.1 R169.1 R170.1 R171.1 R172.1 R174.1 R175.1 R176.1 R177.1 R178.1 R179.1 R180.1 R181.1 R182.1 R183.1 R184.1 R186.1 R187.1 R188.1 R189.1 R190.1 R191.1 R192.1 R193.1 R201.2 ; also on sheet 23 54
2V5_DDR4_COMP: C245.1 C246.1 C247.2 C248.1 C249.1 C250.2 C290.1 C291.1 C292.2 U17.B1(VPP) U17.M9(VPP) U18.B1(VPP) U18.M9(VPP) U19.B1(VPP) U19.M9(VPP) ; also on sheet 25 54
3V3_QSFP: C325.2 C326.2 FB9.2 FB10.2 FB11.2 R221.1 U21.6(OUT1) U21.7(OUT2)
3V3_QSFPDD: C307.1 C308.2 L1.1 L2.1 L3.1 R212.1 U20.6(OUT1) U20.7(OUT2)
3V3_STBY: R206.2 R208.2 ; also on sheet 8 10 16 22 32 34 36 37 38 40 41 48 49 50 51 52 53 54 58
3V3_SYS: C304.2 C305.2 C306.2 C322.2 C323.2 C324.2 R211.2 R215.2 R217.2 R218.2 R220.2 R784.2 R785.2 R6894.2 U20.2(IN1) U20.3(IN2) U21.2(IN1) U21.3(IN2) ; also on sheet 31 32 34 35 36 37 41
12V_PCIE_IN: C295.1 C296.1 J6.1 J6.60 ; also on sheet 40 41 47 49 50 55 56
GND: C243.2 C244.2 C245.2 C246.2 C247.1 C248.2 C249.2 C250.1 C251.2 C252.2 C253.2 C254.2 C255.2 C256.2 C257.2 C258.2 C259.2 C260.2 C261.2 C262.2 C263.2 C264.2 C265.2 C266.2 C267.2 C268.1 C269.1 C270.2 C271.2 C272.2 C273.2 C274.2 C275.2 C276.2 C277.2 C278.2 C279.2 C280.2 C281.2 C282.2 C283.2 C284.2 C285.2 C286.2 C287.2 C288.2 C289.2 C290.2 C291.2 C292.1 C293.2 C295.2 C296.2 C297.2 C298.2 C299.2 C300.2 C301.2 C302.2 C303.2 C304.1 C305.1 C306.1 C307.2 C308.1 C309.2 C310.1 C311.1 C312.1 C313.2 C314.1 C315.1 C316.1 C317.2 C318.1 C319.1 C320.1 C321.2 C322.1 C323.1 C324.1 C325.1 C326.1 C327.1 C328.1 C329.1 C330.1 C331.1 C332.1 C333.1 C334.1 C335.1 C336.1 C337.1 C338.1 C339.2 C966.2 C967.2 C968.2 C969.2 C970.2 C971.2 C972.2 C973.2 C974.2 C975.2 C1225.2 C1226.2 C1227.2 C1228.2 C1229.2 C1230.2 C1231.2 C1232.2 C1233.2 C1234.2 C1235.2 C1236.2 J6.61(GND1) J6.62(GND2) J6.63(GND3) J6.64(GND4) J7.1(GND) J7.4(GND) J7.7(GND) J7.13(GND) J7.16(GND) J7.19(GND) J7.20(GND) J7.23(GND) J7.26(GND) J7.32(GND) J7.35(GND) J7.38(GND) J7.39(GND) J7.42(GND) J7.45(GND) J7.51(GND) J7.54(GND) J7.57(GND) J7.58(GND) J7.61(GND) J7.64(GND) J7.70(GND) J7.73(GND) J7.76(GND) J8.1(GND12) J8.4(GND11) J8.7(GND10) J8.13(GND9) J8.16(GND8) J8.19(GND7) J8.20(GND6) J8.23(GND5) J8.26(GND4) J8.32(GND3) J8.35(GND2) J8.38(GND1) R165.1 R166.1 R173.1 R196.1 R198.1 R199.2 R209.2 R210.2 R212.2 R213.2 R214.1 R219.1 R221.2 R222.2 R223.1 R224.1 U17.A2(VSSQ) U17.A8(VSSQ) U17.A9(VSS) U17.C8(VSS) U17.D1(VSSQ) U17.D9(VSSQ) U17.E1(VSS) U17.E9(VSS) U17.G1(VSS) U17.H9(VSS_H1) U17.K1(VSS) U17.K9(VSS) U17.N1(VSS) U18.A2(VSSQ) U18.A8(VSSQ) U18.A9(VSS) U18.C8(VSS) U18.D1(VSSQ) U18.D9(VSSQ) U18.E1(VSS) U18.E9(VSS) U18.G1(VSS) U18.H9(VSS_H1) U18.K1(VSS) U18.K9(VSS) U18.N1(VSS) U19.A2(VSSQ) U19.A8(VSSQ) U19.A9(VSS) U19.C8(VSS) U19.D1(VSSQ) U19.D9(VSSQ) U19.E1(VSS) U19.E9(VSS) U19.G1(VSS) U19.H9(VSS_H1) U19.K1(VSS) U19.K9(VSS) U19.N1(VSS) U20.1(GND) U20.9(MPAD) U21.1(GND) U21.9(MPAD) ; also on sheet 8 9 10 11 12 13 15 16 19 20 21 22 23 24 25 31 32 33 34 35 36 37 38 39 40 41 42 43 44 45 46 47 48 49 50 51 52 53 54 55 56 58
GND_QSFP_CAGE: B2.1(Pin1) B2.2(Pin2) B2.3(Pin3) B2.4(Pin4) B2.5(Pin5) B2.6(Pin6) B2.7(Pin7) B2.8(Pin8) B2.9(Pin9) B2.10(Pin10) B2.11(Pin11) B2.12(Pin12) C339.1 R224.2
GND_QSFPDD_CAGE: B1.1(Pin1) B1.2(Pin2) B1.3(Pin3) B1.4(Pin4) B1.5(Pin5) B1.6(Pin6) B1.7(Pin7) B1.8(Pin8) B1.9(Pin9) B1.10(Pin10) B1.11(Pin11) B1.12(Pin12) C321.1 R219.2
DDR4_COMP_A0: R167.2 U17.L3(A0) U18.L3(A0) U19.L3(A0) ; also on sheet 19 25
DDR4_COMP_A1: R168.2 U17.L7(A1) U18.L7(A1) U19.L7(A1) ; also on sheet 19 25
DDR4_COMP_A2: R169.2 U17.M3(A2) U18.M3(A2) U19.M3(A2) ; also on sheet 19 25
DDR4_COMP_A3: R170.2 U17.K7(A3) U18.K7(A3) U19.K7(A3) ; also on sheet 19 25
DDR4_COMP_A4: R171.2 U17.K3(A4) U18.K3(A4) U19.K3(A4) ; also on sheet 19 25
DDR4_COMP_A5: R172.2 U17.L8(A5) U18.L8(A5) U19.L8(A5) ; also on sheet 19 25
DDR4_COMP_A6: R174.2 U17.L2(A6) U18.L2(A6) U19.L2(A6) ; also on sheet 19 25
DDR4_COMP_A7: R175.2 U17.M8(A7) U18.M8(A7) U19.M8(A7) ; also on sheet 19 25
DDR4_COMP_A8: R176.2 U17.M2(A8) U18.M2(A8) U19.M2(A8) ; also on sheet 19 25
DDR4_COMP_A9: R177.2 U17.M7(A9) U18.M7(A9) U19.M7(A9) ; also on sheet 19 25
DDR4_COMP_A10: R178.2 U17.J3(A10/AP) U18.J3(A10/AP) U19.J3(A10/AP) ; also on sheet 19 25
DDR4_COMP_A11: R179.2 U17.N2(A11) U18.N2(A11) U19.N2(A11) ; also on sheet 19 25
DDR4_COMP_A12: R180.2 U17.J7(A12/BC_N) U18.J7(A12/BC_N) U19.J7(A12/BC_N) ; also on sheet 19 25
DDR4_COMP_A13: R181.2 U17.N8(A13) U18.N8(A13) U19.N8(A13) ; also on sheet 19 25
DDR4_COMP_A14: R182.2 U17.H2(WE_N/A14) U18.H2(WE_N/A14) U19.H2(WE_N/A14) ; also on sheet 19 25
DDR4_COMP_A15: R183.2 U17.H7(CAS_N/A15) U18.H7(CAS_N/A15) U19.H7(CAS_N/A15) ; also on sheet 19 25
DDR4_COMP_A16: R184.2 U17.H8(RAS_N/A16) U18.H8(RAS_N/A16) U19.H8(RAS_N/A16) ; also on sheet 19 25
DDR4_COMP_ACT_N: R192.2 U17.H3(ACT_N) U18.H3(ACT_N) U19.H3(ACT_N) ; also on sheet 19 25
DDR4_COMP_ALERT_N: R194.2 U17.L9(ALERT_N) U18.L9(ALERT_N) U19.L9(ALERT_N) ; also on sheet 19 25
DDR4_COMP_BA0: R188.2 U17.K2(BA0) U18.K2(BA0) U19.K2(BA0) ; also on sheet 19 25
DDR4_COMP_BA1: R189.2 U17.K8(BA1) U18.K8(BA1) U19.K8(BA1) ; also on sheet 19 25
DDR4_COMP_BG0: R186.2 U17.J2(BG0) U18.J2(BG0) U19.J2(BG0) ; also on sheet 19 25
DDR4_COMP_BG1: R187.2 U17.J8(BG1) U18.J8(BG1) U19.J8(BG1) ; also on sheet 19 25
DDR4_COMP_CK_N: R202.2 U17.F8(CK_C) U18.F8(CK_C) U19.F8(CK_C) ; also on sheet 19 25
DDR4_COMP_CK_P: R200.2 U17.F7(CK_T) U18.F7(CK_T) U19.F7(CK_T) ; also on sheet 19 25
DDR4_COMP_CKE: R198.2 R201.1 U17.G3(CKE) U18.G3(CKE) U19.G3(CKE) ; also on sheet 19 25
DDR4_COMP_CS_N: R190.2 U17.G7(CS_N) U18.G7(CS_N) U19.G7(CS_N) ; also on sheet 19 25
DDR4_COMP_DBI_N0: U19.A7(NF/DM_N/DBI_N/TDQS_T) ; also on sheet 19
DDR4_COMP_DBI_N2: U17.A7(NF/DM_N/DBI_N/TDQS_T) ; also on sheet 19
DDR4_COMP_DBI_N3: U18.A7(NF/DM_N/DBI_N/TDQS_T) ; also on sheet 19
DDR4_COMP_DQ0: U19.C2(DQ0) ; also on sheet 19
DDR4_COMP_DQ1: U19.B7(DQ1) ; also on sheet 19
DDR4_COMP_DQ2: U19.D3(DQ2) ; also on sheet 19
DDR4_COMP_DQ3: U19.D7(DQ3) ; also on sheet 19
DDR4_COMP_DQ4: U19.D2(DQ4) ; also on sheet 19
DDR4_COMP_DQ5: U19.D8(DQ5) ; also on sheet 19
DDR4_COMP_DQ6: U19.E3(DQ6) ; also on sheet 19
DDR4_COMP_DQ7: U19.E7(DQ7) ; also on sheet 19
DDR4_COMP_DQ16: U17.C2(DQ0) ; also on sheet 19
DDR4_COMP_DQ17: U17.B7(DQ1) ; also on sheet 19
DDR4_COMP_DQ18: U17.D3(DQ2) ; also on sheet 19
DDR4_COMP_DQ19: U17.D7(DQ3) ; also on sheet 19
DDR4_COMP_DQ20: U17.D2(DQ4) ; also on sheet 19
DDR4_COMP_DQ21: U17.D8(DQ5) ; also on sheet 19
DDR4_COMP_DQ22: U17.E3(DQ6) ; also on sheet 19
DDR4_COMP_DQ23: U17.E7(DQ7) ; also on sheet 19
DDR4_COMP_DQ24: U18.C2(DQ0) ; also on sheet 19
DDR4_COMP_DQ25: U18.B7(DQ1) ; also on sheet 19
DDR4_COMP_DQ26: U18.D3(DQ2) ; also on sheet 19
DDR4_COMP_DQ27: U18.D7(DQ3) ; also on sheet 19
DDR4_COMP_DQ28: U18.D2(DQ4) ; also on sheet 19
DDR4_COMP_DQ29: U18.D8(DQ5) ; also on sheet 19
DDR4_COMP_DQ30: U18.E3(DQ6) ; also on sheet 19
DDR4_COMP_DQ31: U18.E7(DQ7) ; also on sheet 19
DDR4_COMP_DQS_N0: U19.B3(DQS_C) ; also on sheet 19
DDR4_COMP_DQS_N2: U17.B3(DQS_C) ; also on sheet 19
DDR4_COMP_DQS_N3: U18.B3(DQS_C) ; also on sheet 19
DDR4_COMP_DQS_P0: U19.C3(DQS_T) ; also on sheet 19
DDR4_COMP_DQS_P2: U17.C3(DQS_T) ; also on sheet 19
DDR4_COMP_DQS_P3: U18.C3(DQS_T) ; also on sheet 19
DDR4_COMP_ODT: R191.2 U17.F3(ODT) U18.F3(ODT) U19.F3(ODT) ; also on sheet 19 25
DDR4_COMP_PAR: R193.2 U17.N3(PAR) U18.N3(PAR) U19.N3(PAR) ; also on sheet 19 25
DDR4_COMP_RESET_N: R195.2 R196.2 U17.L1(RESET_N) U18.L1(RESET_N) U19.L1(RESET_N) ; also on sheet 19 25
DDR4_COMP_TEN: R197.2 R199.1 U17.G9(TEN/NF) U18.G9(TEN/NF) U19.G9(TEN/NF) ; also on sheet 25
FPGA_3V3_SCL: J7.11(SCL) J8.11(SCL) ; also on sheet 16 35 37
FPGA_3V3_SDA: J7.12(SDA) J8.12(SDA) ; also on sheet 16 35 37
FPGA_VCCIO_1V2: C251.1 C252.1 C253.1 C254.1 C255.1 C256.1 C257.1 C258.1 C259.1 C260.1 C261.1 C262.1 C263.1 C264.1 C265.1 C266.1 C267.1 C268.2 C269.2 C270.1 C271.1 C272.1 C273.1 C274.1 C275.1 C276.1 C277.1 C278.1 C279.1 C280.1 C281.1 C282.1 C283.1 C284.1 C285.1 C286.1 C287.1 C288.1 C966.1 C967.1 C968.1 C969.1 C970.1 C971.1 C972.1 C973.1 C974.1 C975.1 R194.1 R195.1 R197.1 U17.A1(VDD) U17.B2(VDDQ) U17.B8(VDDQ) U17.C1(VDDQ) U17.C7(VDD) U17.C9(VDDQ) U17.E2(VDDQ) U17.E8(VDDQ) U17.F1(VDD) U17.F9(VDD) U17.H1(VDD) U17.J9(VDD) U17.M1(VDD) U17.N9(VDD) U18.A1(VDD) U18.B2(VDDQ) U18.B8(VDDQ) U18.C1(VDDQ) U18.C7(VDD) U18.C9(VDDQ) U18.E2(VDDQ) U18.E8(VDDQ) U18.F1(VDD) U18.F9(VDD) U18.H1(VDD) U18.J9(VDD) U18.M1(VDD) U18.N9(VDD) U19.A1(VDD) U19.B2(VDDQ) U19.B8(VDDQ) U19.C1(VDDQ) U19.C7(VDD) U19.C9(VDDQ) U19.E2(VDDQ) U19.E8(VDDQ) U19.F1(VDD) U19.F9(VDD) U19.H1(VDD) U19.J9(VDD) U19.M1(VDD) U19.N9(VDD) ; also on sheet 10 16 23 25 31 34 35 36 39 50 54 55 56
FPGA_VCCIO_SDM_HPS: R204.2 R205.2 R207.2 ; also on sheet 11 23 33 35 39 52 53
FPGA_VCCPT: C297.1 C298.1 C299.1 C300.1 C301.1 C302.1 J6.2 J6.59 ; also on sheet 23 39 50 51
HPS_CON_GPIO26: J6.29 ; also on sheet 22
HPS_CON_GPIO27: J6.30 ; also on sheet 22
HPS_DC_PG: J6.54 R206.1 ; also on sheet 10
HPS_DC_PRSENT_N: J6.52 R208.1 ; also on sheet 10
HPS_DC_PWR_EN: J6.51 R209.1 ; also on sheet 10
HPS_DC_RST_N: J6.53 R207.1 R210.1 ; also on sheet 10
HPS_GPIO0: J6.3 ; also on sheet 22
HPS_GPIO1: J6.4 ; also on sheet 22
HPS_GPIO2: J6.5 ; also on sheet 22
HPS_GPIO3: J6.6 ; also on sheet 22
HPS_GPIO4: J6.7 ; also on sheet 22
HPS_GPIO5: J6.8 ; also on sheet 22
HPS_GPIO6: J6.9 ; also on sheet 22
HPS_GPIO7: J6.10 ; also on sheet 22
HPS_GPIO8: J6.11 ; also on sheet 22
HPS_GPIO9: J6.12 ; also on sheet 22
HPS_GPIO10: J6.13 ; also on sheet 22
HPS_GPIO11: J6.14 ; also on sheet 22
HPS_GPIO12: J6.15 ; also on sheet 22
HPS_GPIO13: J6.16 ; also on sheet 22
HPS_GPIO14: J6.17 ; also on sheet 22
HPS_GPIO15: J6.18 ; also on sheet 22
HPS_GPIO16: J6.19 ; also on sheet 22
HPS_GPIO17: J6.20 ; also on sheet 22
HPS_GPIO18: J6.21 ; also on sheet 22
HPS_GPIO19: J6.22 ; also on sheet 22
HPS_GPIO20: J6.23 ; also on sheet 22
HPS_GPIO21: J6.24 ; also on sheet 22
HPS_GPIO22: J6.25 ; also on sheet 22
HPS_GPIO23: J6.26 ; also on sheet 22
HPS_GPIO24: J6.27 ; also on sheet 22
HPS_GPIO25: J6.28 ; also on sheet 22
HPS_GPIO28: J6.31 ; also on sheet 22
HPS_GPIO29: J6.32 ; also on sheet 22
HPS_GPIO30: J6.33 R204.1 ST1.1 ; also on sheet 22
HPS_GPIO31: J6.34 R203.2 R205.1 ST2.1 ; also on sheet 22
HPS_GPIO32: J6.35 ; also on sheet 22
HPS_GPIO33: J6.36 ; also on sheet 22
HPS_GPIO34: J6.37 ; also on sheet 22
HPS_GPIO35: J6.38 ; also on sheet 22
HPS_GPIO36: J6.39 ; also on sheet 22
HPS_GPIO37: J6.40 ; also on sheet 22
HPS_GPIO38: J6.41 ; also on sheet 22
HPS_GPIO39: J6.42 ; also on sheet 22
HPS_GPIO40: J6.43 ; also on sheet 22
HPS_GPIO41: J6.44 ; also on sheet 22
HPS_GPIO42: J6.45 ; also on sheet 22
HPS_GPIO43: J6.46 ; also on sheet 22
HPS_GPIO44: J6.47 ; also on sheet 22
HPS_GPIO45: J6.48 ; also on sheet 22
HPS_GPIO46: J6.49 ; also on sheet 22
HPS_GPIO47: J6.50 ; also on sheet 22
HPS_SCL: ST2.2 ; also on sheet 10
HPS_SDA: ST1.2 ; also on sheet 10
HPS_TCK: J6.55 ; also on sheet 10
HPS_TDI: J6.56 ; also on sheet 10
HPS_TDO: J6.58 ; also on sheet 10
HPS_TMS: J6.57 ; also on sheet 10
QSFP_3V3_INT_L: J7.28(INTL) J8.28(Intl) R217.1 R784.1 ; also on sheet 16
QSFP_3V3_LPMODE: J8.31(LPMode) ; also on sheet 16
QSFP_3V3_MODPRS_L: J8.27(ModPrsL) R785.1 ; also on sheet 10 16
QSFP_3V3_RESET_L: J7.9(RESETL) J8.9(ResetL) ; also on sheet 16
QSFP_3V3_SELn: J8.8(ModselL) R6894.1 ; also on sheet 16
QSFP_FAULT_N: R220.1 U21.8(~{FAULT}) ; also on sheet 10
QSFP_PWR_EN: R223.2 U21.4(EN) ; also on sheet 10
QSFP_RX0_N: J8.18(RX1n) ; also on sheet 20
QSFP_RX0_P: J8.17(RX1p) ; also on sheet 20
QSFP_RX1_N: J8.21(RX2n) ; also on sheet 20
QSFP_RX1_P: J8.22(RX2p) ; also on sheet 20
QSFP_RX2_N: J8.15(RX3n) ; also on sheet 20
QSFP_RX2_P: J8.14(RX3p) ; also on sheet 20
QSFP_RX3_N: J8.24(RX4n) ; also on sheet 20
QSFP_RX3_P: J8.25(RX4p) ; also on sheet 20
QSFP_TX0_N: J8.37(TX1n) ; also on sheet 20
QSFP_TX0_P: J8.36(TX1p) ; also on sheet 20
QSFP_TX1_N: J8.2(TX2n) ; also on sheet 20
QSFP_TX1_P: J8.3(TX2p) ; also on sheet 20
QSFP_TX2_N: J8.34(TX3n) ; also on sheet 20
QSFP_TX2_P: J8.33(TX3p) ; also on sheet 20
QSFP_TX3_N: J8.5(TX4n) ; also on sheet 20
QSFP_TX3_P: J8.6(TX4p) ; also on sheet 20
QSFP_VCC: C335.2 C336.2 C337.2 C338.2 FB11.1 J8.30(VCC1)
QSFP_VCCR: C331.2 C332.2 C333.2 C334.2 FB10.1 J8.10(VCCRX)
QSFP_VCCT: C327.2 C328.2 C329.2 C330.2 FB9.1 J8.29(VCCTX)
QSFPDD_3V3_LPMODE: J7.31(INITMODE) ; also on sheet 16
QSFPDD_3V3_MODPRS_L: J7.27(MODPRSL) R218.1 ; also on sheet 10 16
QSFPDD_3V3_SELn: J7.8(MODSELL) R215.1 ; also on sheet 16
QSFPDD_FAULT_N: R211.1 U20.8(~{FAULT}) ; also on sheet 10
QSFPDD_PWR_EN: R214.2 U20.4(EN) ; also on sheet 10
QSFPDD_RX0_N: J7.18(RX1N) ; also on sheet 20
QSFPDD_RX0_P: J7.17(RX1P) ; also on sheet 20
QSFPDD_RX1_N: J7.21(RX2N) ; also on sheet 20
QSFPDD_RX1_P: J7.22(RX2P) ; also on sheet 20
QSFPDD_RX2_N: J7.15(RX3N) ; also on sheet 20
QSFPDD_RX2_P: J7.14(RX3P) ; also on sheet 20
QSFPDD_RX3_N: J7.24(RX4N) ; also on sheet 20
QSFPDD_RX3_P: J7.25(RX4P) ; also on sheet 20
QSFPDD_RX4_N: J7.56(RX5N) ; also on sheet 20
QSFPDD_RX4_P: J7.55(RX5P) ; also on sheet 20
QSFPDD_RX5_N: J7.59(RX6N) ; also on sheet 20
QSFPDD_RX5_P: J7.60(RX6P) ; also on sheet 20
QSFPDD_RX6_N: J7.53(RX7N) ; also on sheet 20
QSFPDD_RX6_P: J7.52(RX7P) ; also on sheet 20
QSFPDD_RX7_N: J7.62(RX8N) ; also on sheet 20
QSFPDD_RX7_P: J7.63(RX8P) ; also on sheet 20
QSFPDD_TX0_N: J7.37(TX1N) ; also on sheet 20
QSFPDD_TX0_P: J7.36(TX1P) ; also on sheet 20
QSFPDD_TX1_N: J7.2(TX2N) ; also on sheet 20
QSFPDD_TX1_P: J7.3(TX2P) ; also on sheet 20
QSFPDD_TX2_N: J7.34(TX3N) ; also on sheet 20
QSFPDD_TX2_P: J7.33(TX3P) ; also on sheet 20
QSFPDD_TX3_N: J7.5(TX4N) ; also on sheet 20
QSFPDD_TX3_P: J7.6(TX4P) ; also on sheet 20
QSFPDD_TX4_N: J7.75(TX5N) ; also on sheet 20
QSFPDD_TX4_P: J7.74(TX5P) ; also on sheet 20
QSFPDD_TX5_N: J7.40(TX6N) ; also on sheet 20
QSFPDD_TX5_P: J7.41(TX6P) ; also on sheet 20
QSFPDD_TX6_N: J7.72(TX7N) ; also on sheet 20
QSFPDD_TX6_P: J7.71(TX7P) ; also on sheet 20
QSFPDD_TX7_N: J7.43(TX8N) ; also on sheet 20
QSFPDD_TX7_P: J7.44(TX8P) ; also on sheet 20
QSFPDD_VCC: C317.1 C318.2 C319.2 C320.2 J7.30(VCC1) J7.68(VCC2) L3.2
QSFPDD_VCCR: C313.1 C314.2 C315.2 C316.2 J7.10(VCCRX) J7.48(VCCRX1) L2.2
QSFPDD_VCCT: C309.1 C310.2 C311.2 C312.2 J7.29(VCCTX) J7.67(VCCTX1) L1.2
N133159: C293.1 R200.1 R202.1
N140679: R222.1 U21.5(ILIM)
N744808: R213.1 U20.5(ILIM)
N748119: C303.1 R203.1
N1083557: R165.2 U17.B9(ZQ)
N1083575: R166.2 U18.B9(ZQ)
N2153801: R173.2 U19.B9(ZQ)

Not connected (* = marked no-connect by the designer): J7 46(RESERVED1)* 47(VS1)* 49(VS2)* 50(VS3)* 65(NC)* 66(RESERVED2)* 69(RESERVED3)* 77(MTH1)* 78(MTH2)*; J8 39(MTH1)* 40(MTH2)*; U17 A3(NF/TDQS_C)* F2(C2/ODT1/NC)* G2(C0/CKE1/NC)* G8(C1/CS1_N/NC)* N7(NF)*; U18 A3(NF/TDQS_C)* F2(C2/ODT1/NC)* G2(C0/CKE1/NC)* G8(C1/CS1_N/NC)* N7(NF)*; U19 A3(NF/TDQS_C)* F2(C2/ODT1/NC)* G2(C0/CKE1/NC)* G8(C1/CS1_N/NC)* N7(NF)*

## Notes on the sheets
sheet 26
- DDR4 COMPONENT #3/#4
sheet 27
- DDR4 COMPONENT #5 & Termination
sheet 28
- HPS IO-48 Daughter Card Connector
- (HPS_GPIO42 = 25MHz HPS CLK from HPS IO48 Daughter Card)
- 1K pull to GND on HPS Daughter Card
- GND on HPS Daughter Card
- 4.7K pullup to 1.8V on HPS Daughter Card
- 4.7K I2C Pullups to 1.8V on HPS Daughter Card
sheet 29
- Ios Limit = 3.656A / 4.039A / 4.349A
- Rds(on) max = 35mOhm
  dropout max = 4A x .035 = 0.14V
- Route trace
  short as
  possible
- 60uA
- ABSMAX = 7V
- Vil=0.66V
  Vih=1.1V
- QSFPDD-56
- ABSMAX = 7V
- NOTE 1: Bypass Capacitors should be placed as close to the associated 20-pin
  connector as possible.
- NOTE 2: zQSFP 100-ohm termination is implemented via the FPGA on-chip termination.
- NOTE 3: DC blocking capacitors are in the module for RX and TX.
- NOTE 4: 1uH inductors should have a DC Resistance of less than 0.1-ohm.
- RESETL pull high in module
- LPMODE pull high in module
- MODPRSL is GND on Module
- INTL is open collector
- Place close to QSFPDD Connector
- Pull-ups on pg 38
- Amphenol UE36-C16221-06A4A
- Guide Pins
- Guide Pins
- Amphenol UE36-A1015-2000T
sheet 30
- Ios Limit = 3.656A / 4.039A / 4.349A
- NOTE 1: Bypass Capacitors should be placed as close to the associated 20-pin
  connector as possible.
- Rds(on) max = 35mOhm
  dropout max = 4A x .035 = 0.14V
- NOTE 2: zQSFP 100-ohm termination is implemented via the FPGA on-chip termination.
- NOTE 3: DC blocking capacitors are in the module for RX and TX.
- NOTE 4: 1uH inductors should have a DC Resistance of less than 0.1-ohm.
- Route trace
  short as
  possible
- 60uA
- ABSMAX = 7V
- Vil=0.66V
  Vih=1.1V
- ABSMAX = 7V
- Place close to zQSFP Connector
- RESETL pull high in module
- MODPRSL is GND on Module
- LPMODEL pull high in module
- INTL is open collector
- Amphenol U95-T1C1-101A
- Pull-ups on pg 38
- Pullup on pg32
- Guide Pins
- Guide Pins
- Amphenol FS1-K38-20ZA-A0
